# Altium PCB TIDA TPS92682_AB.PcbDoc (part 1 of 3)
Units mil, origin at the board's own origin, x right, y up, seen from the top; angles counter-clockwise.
Board outline 3149 x 2999 mil, 6 copper layers (Top Layer, Signal Layer 1, Signal Layer 2, Signal Layer 3, Signal Layer 4, Bottom Layer), stack 61.4 mil thick; 281 components, 181 nets, 796 pads, 814 vias.
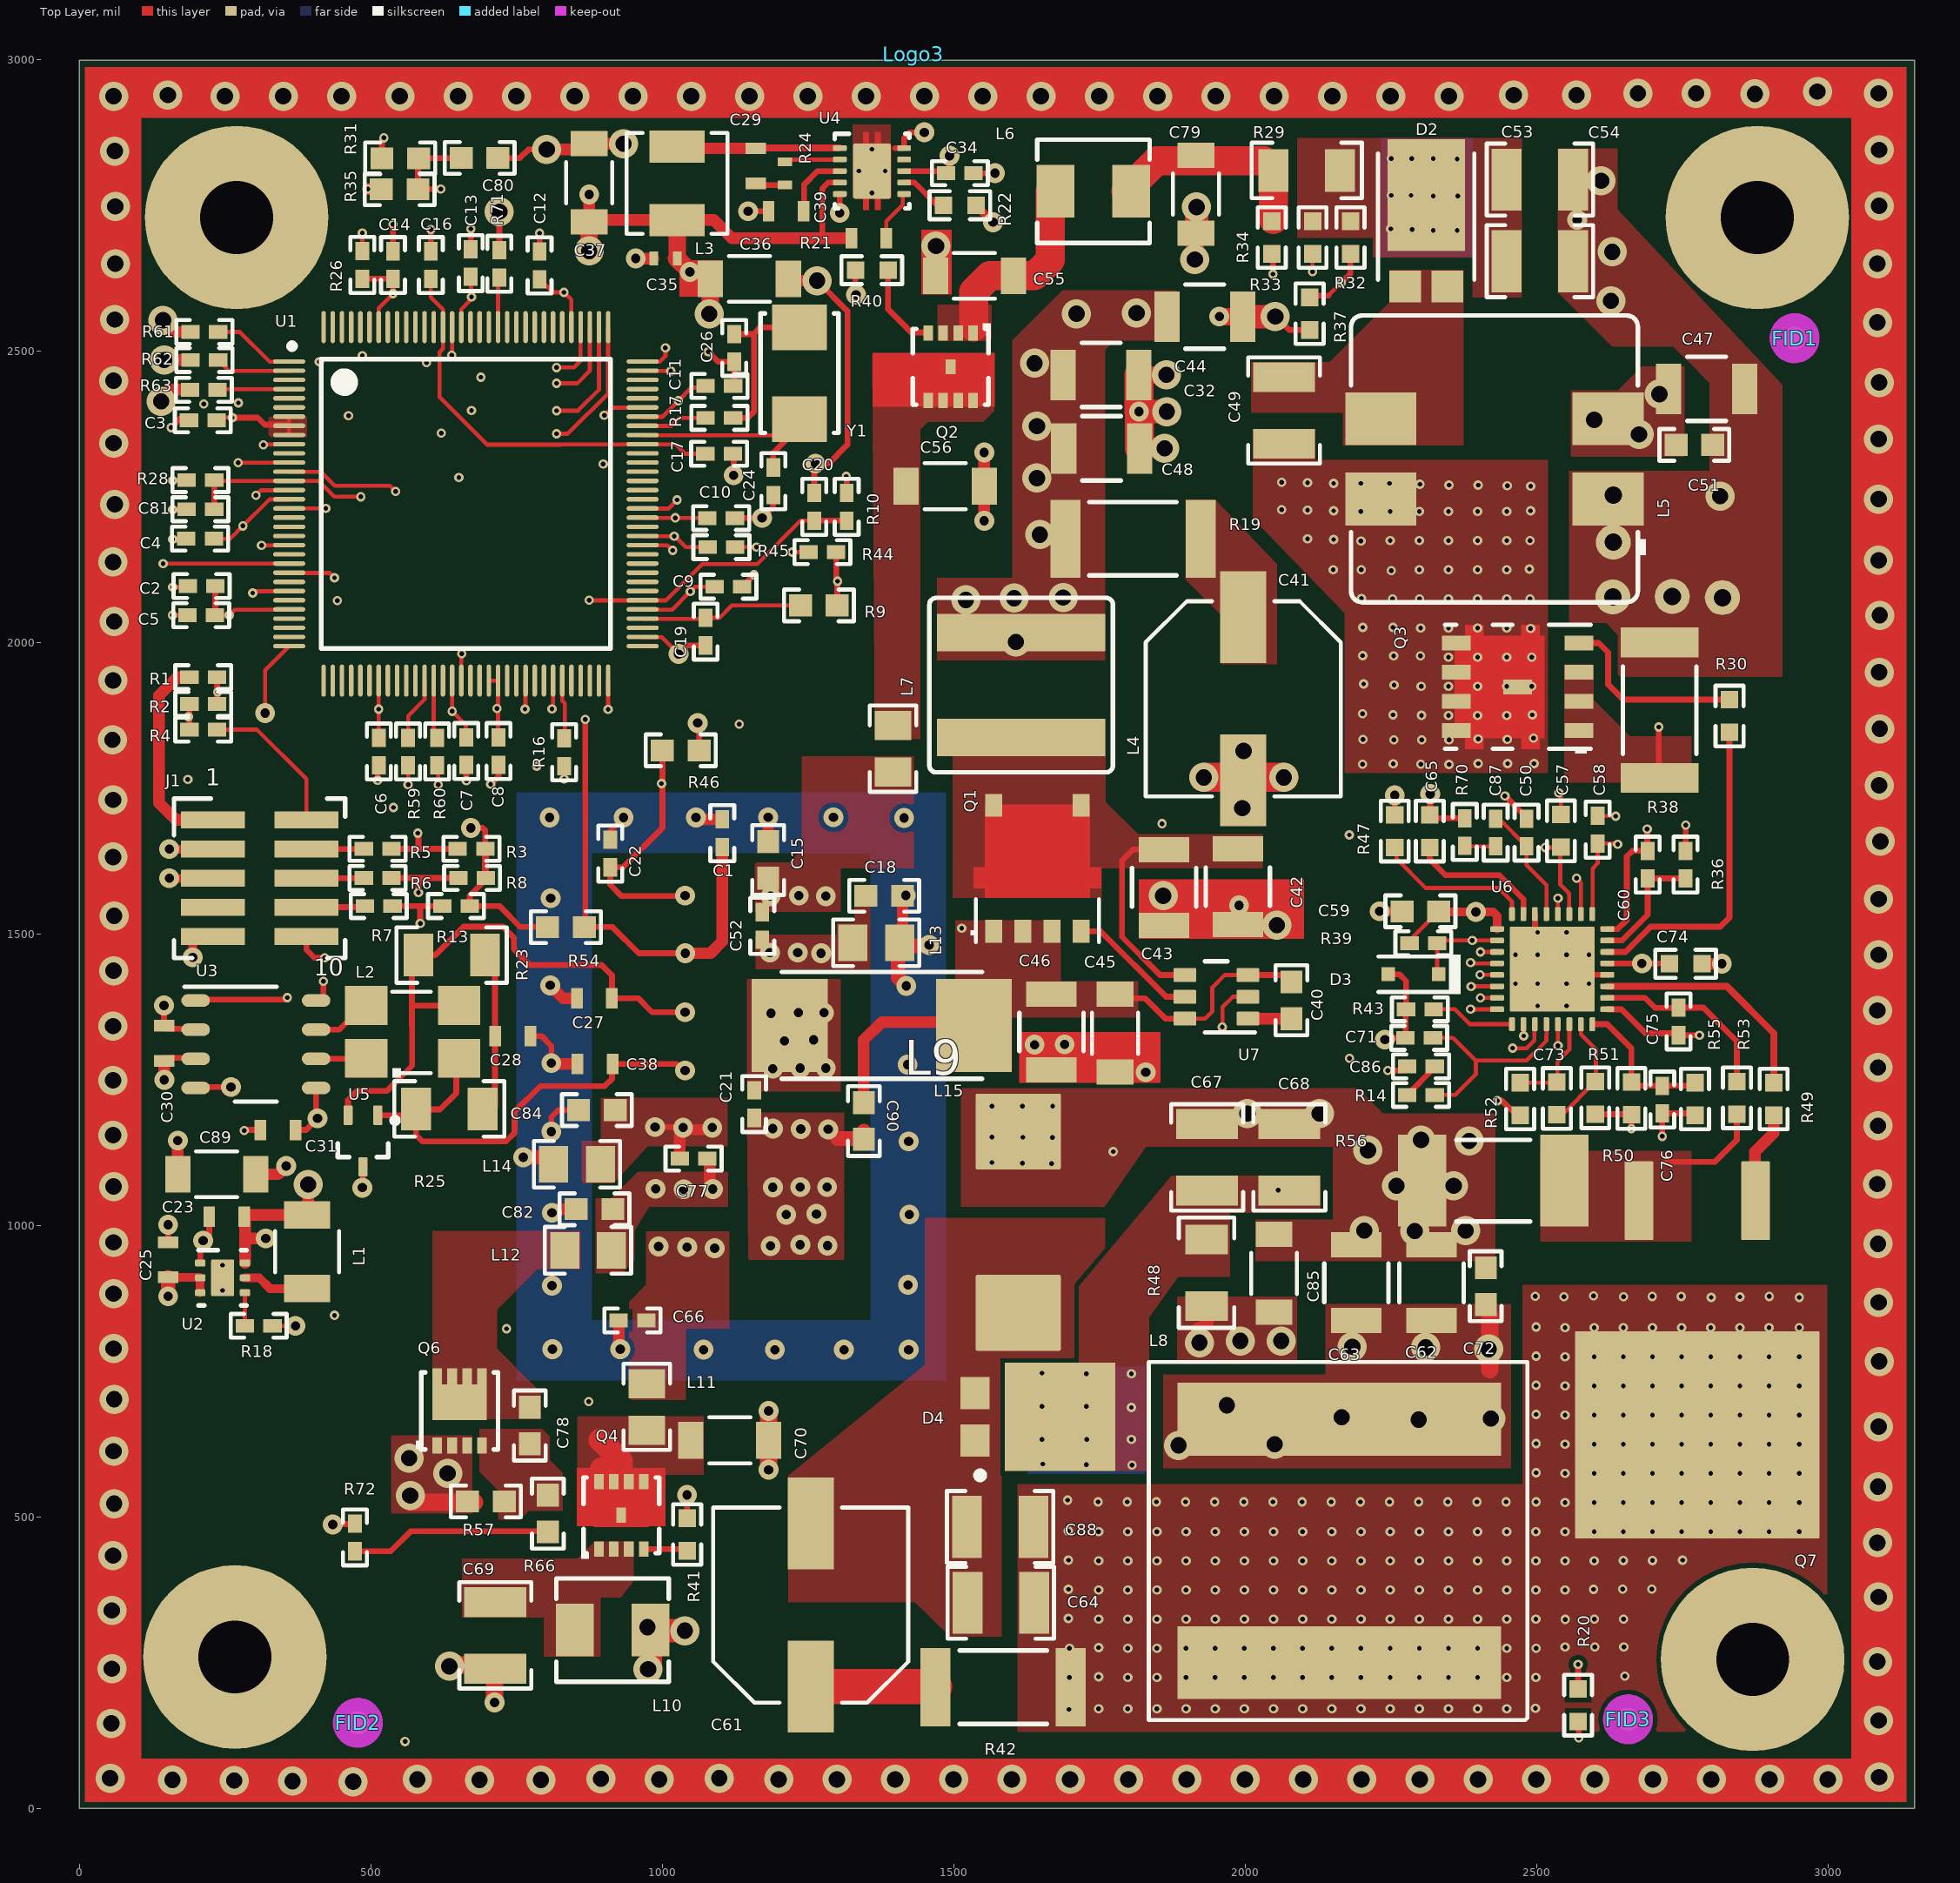
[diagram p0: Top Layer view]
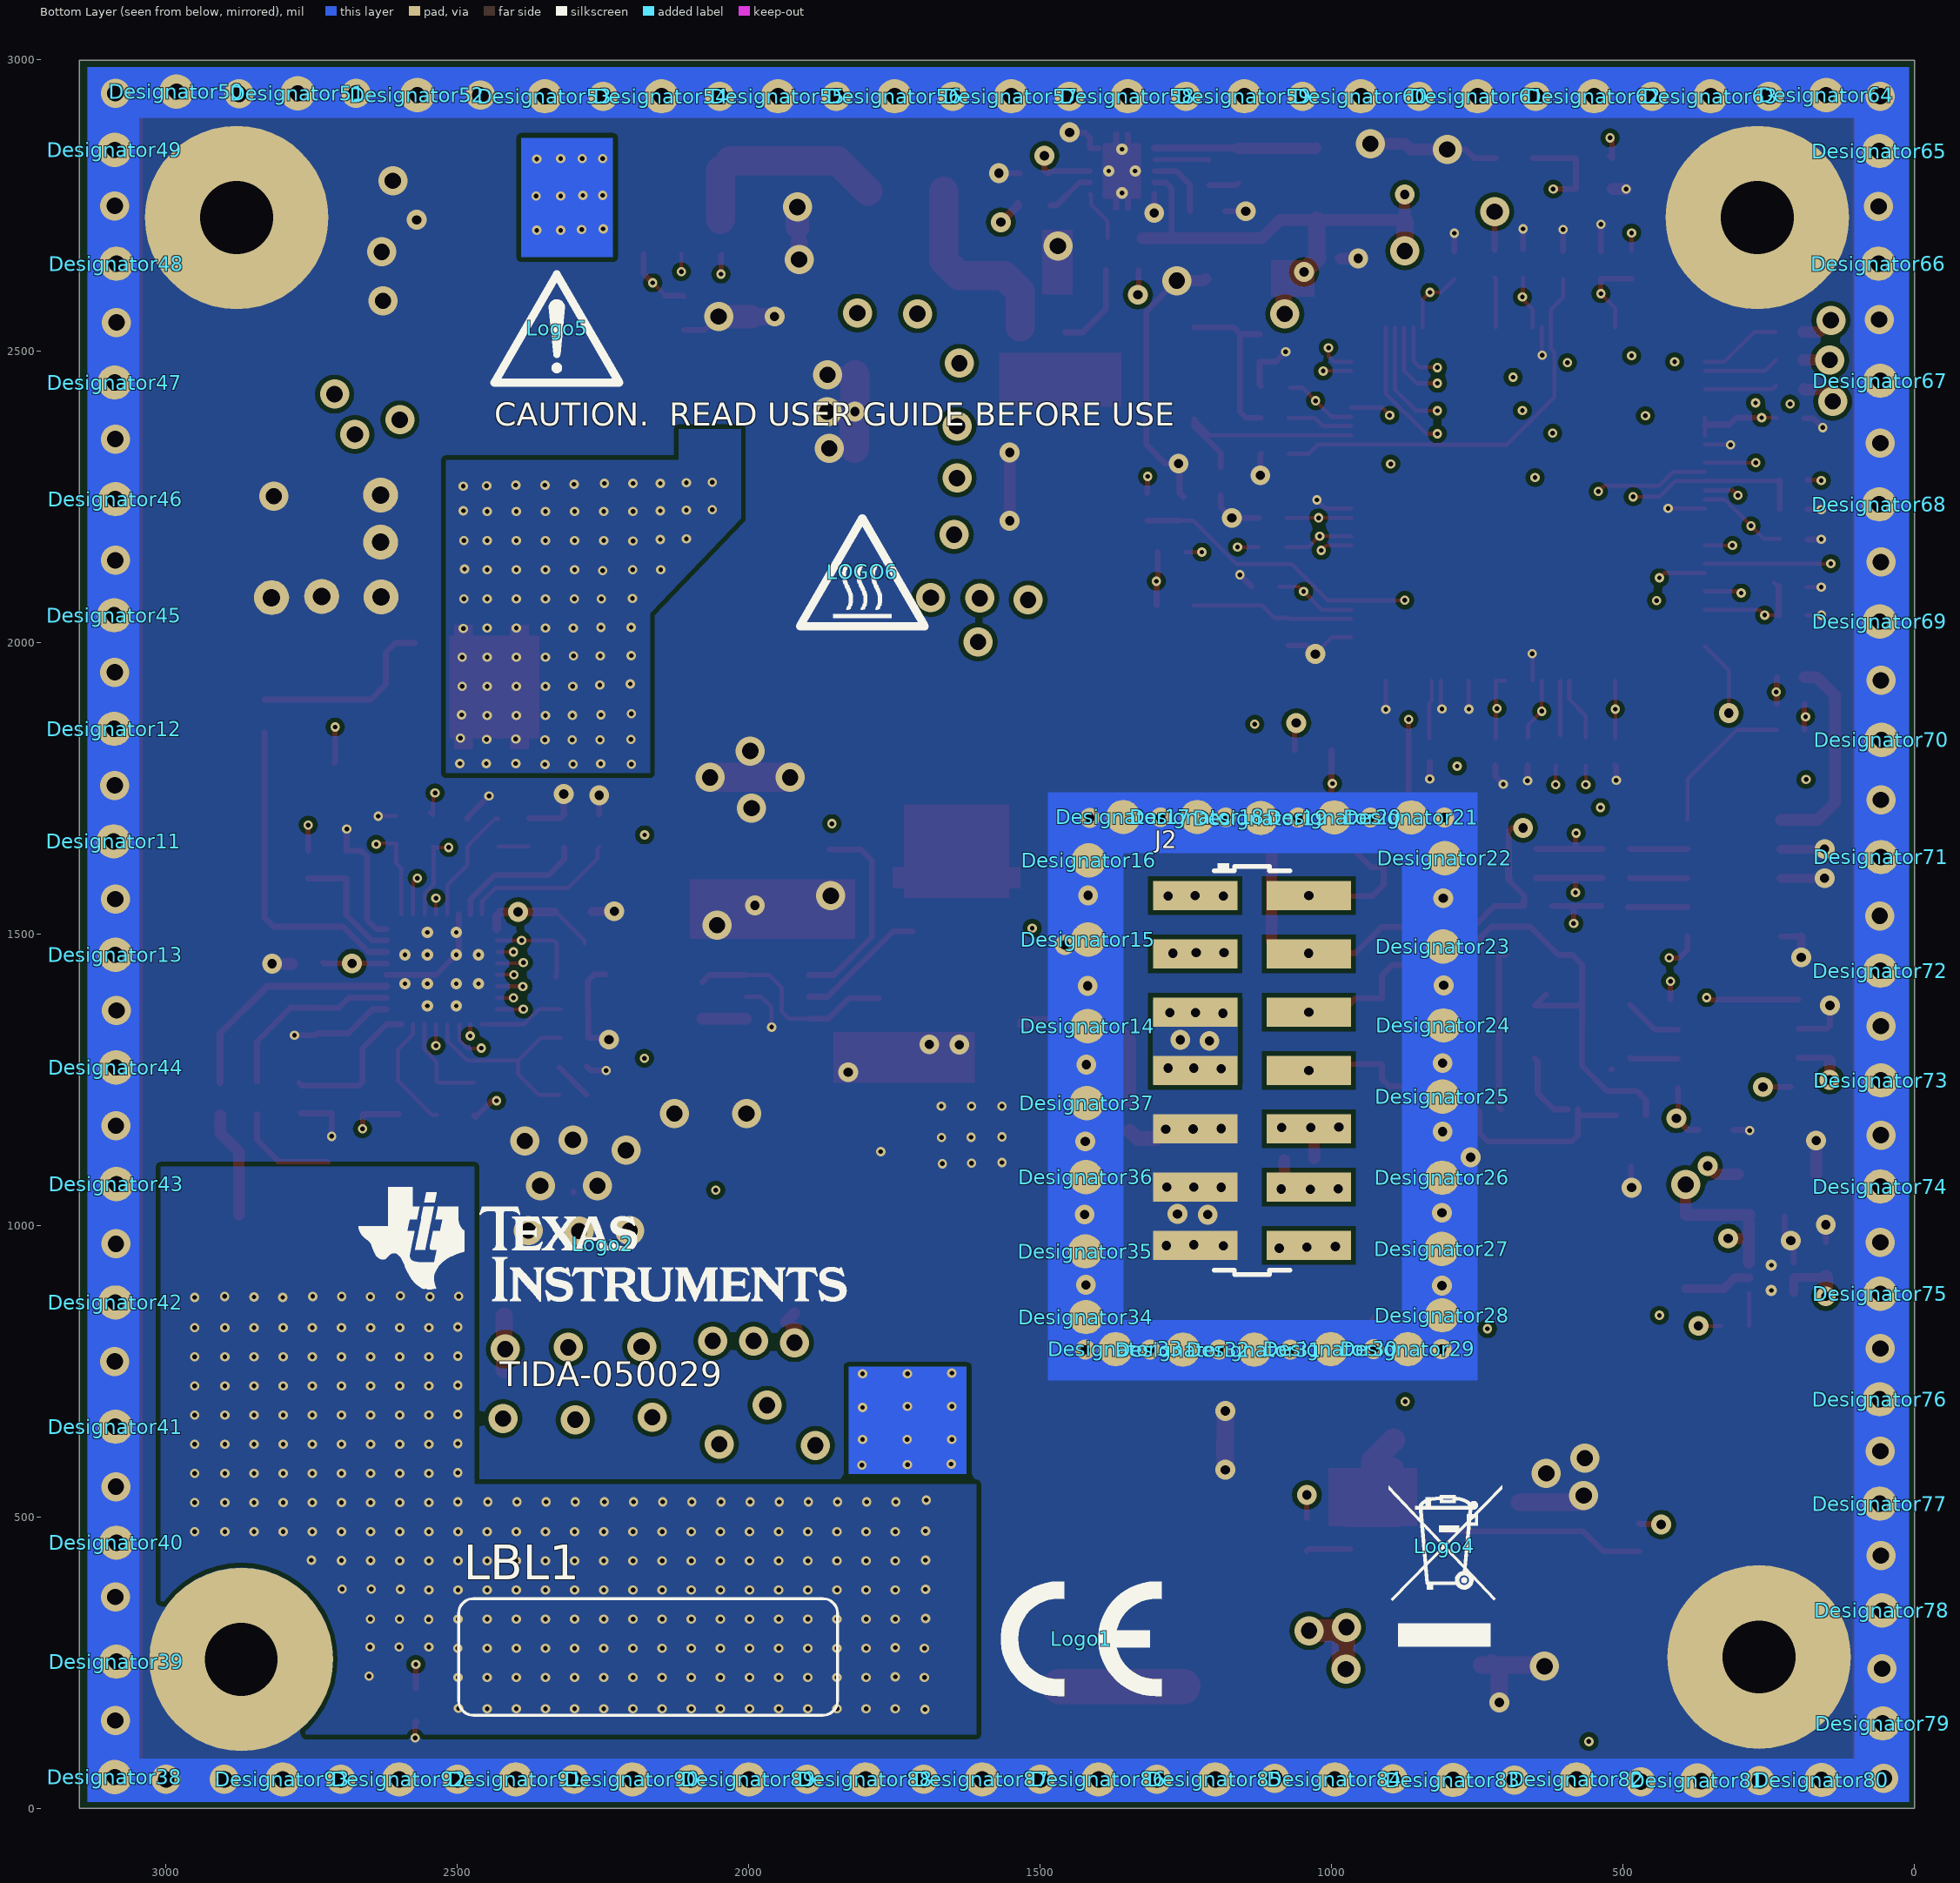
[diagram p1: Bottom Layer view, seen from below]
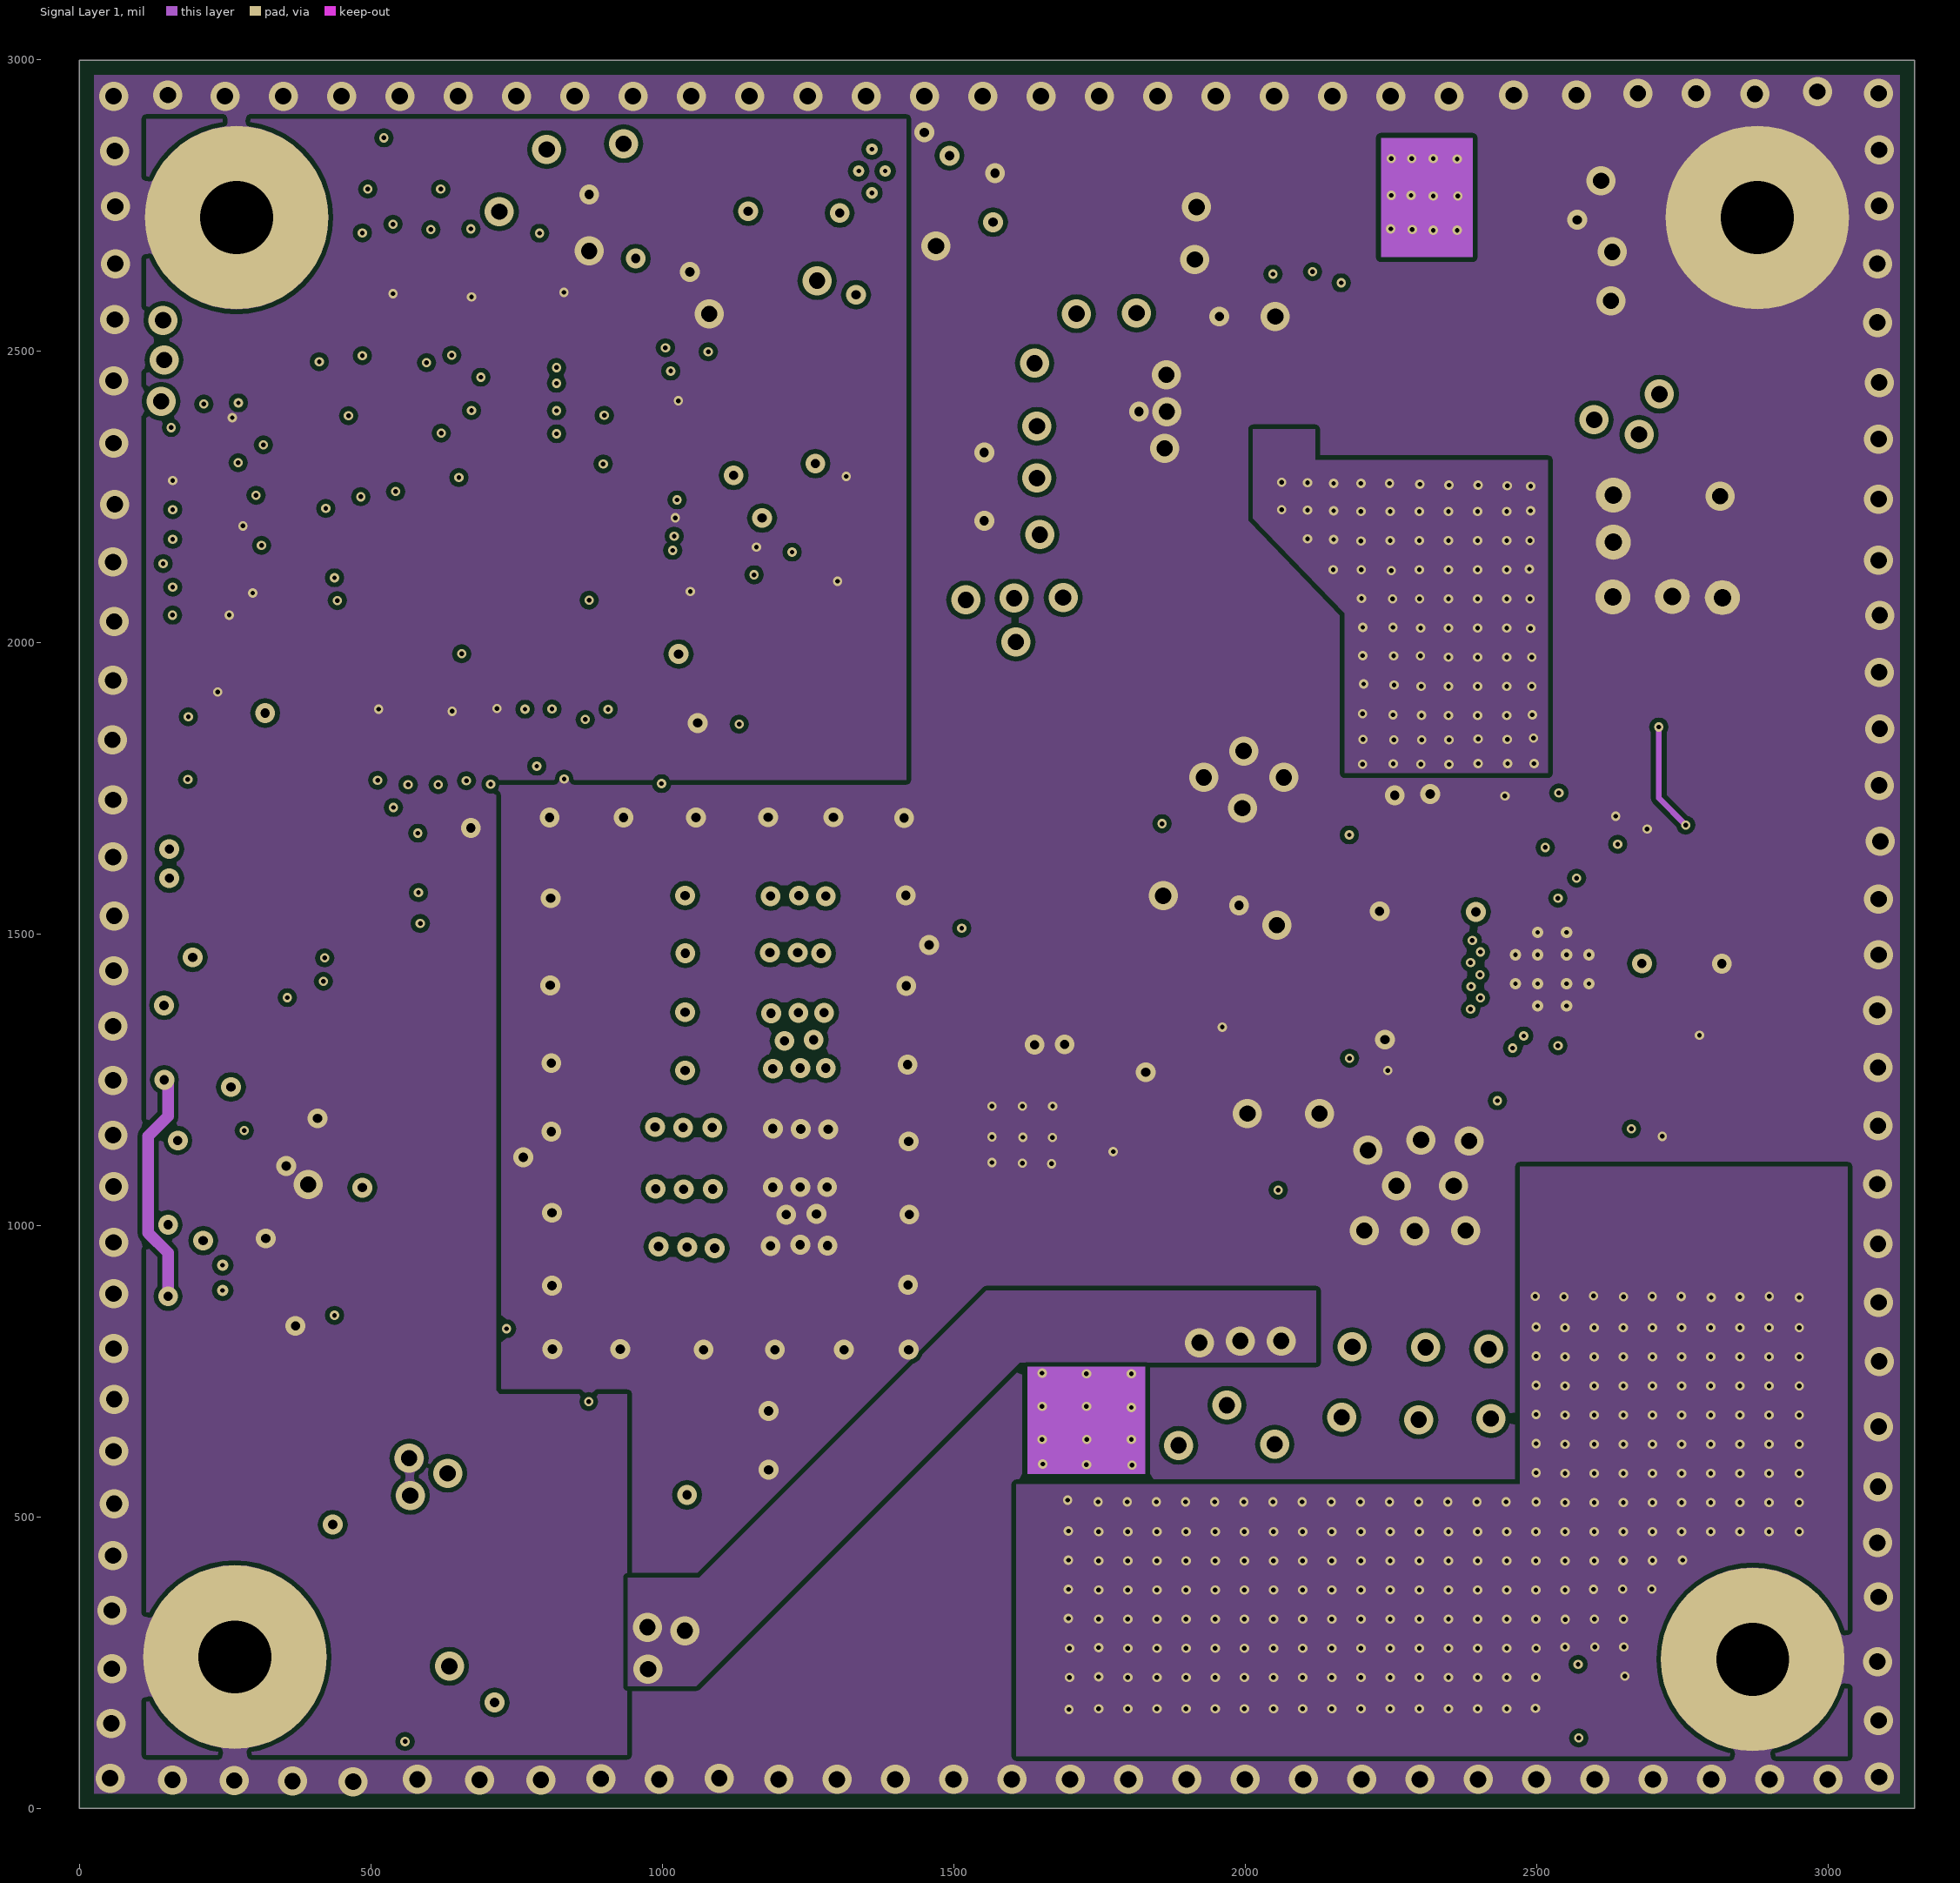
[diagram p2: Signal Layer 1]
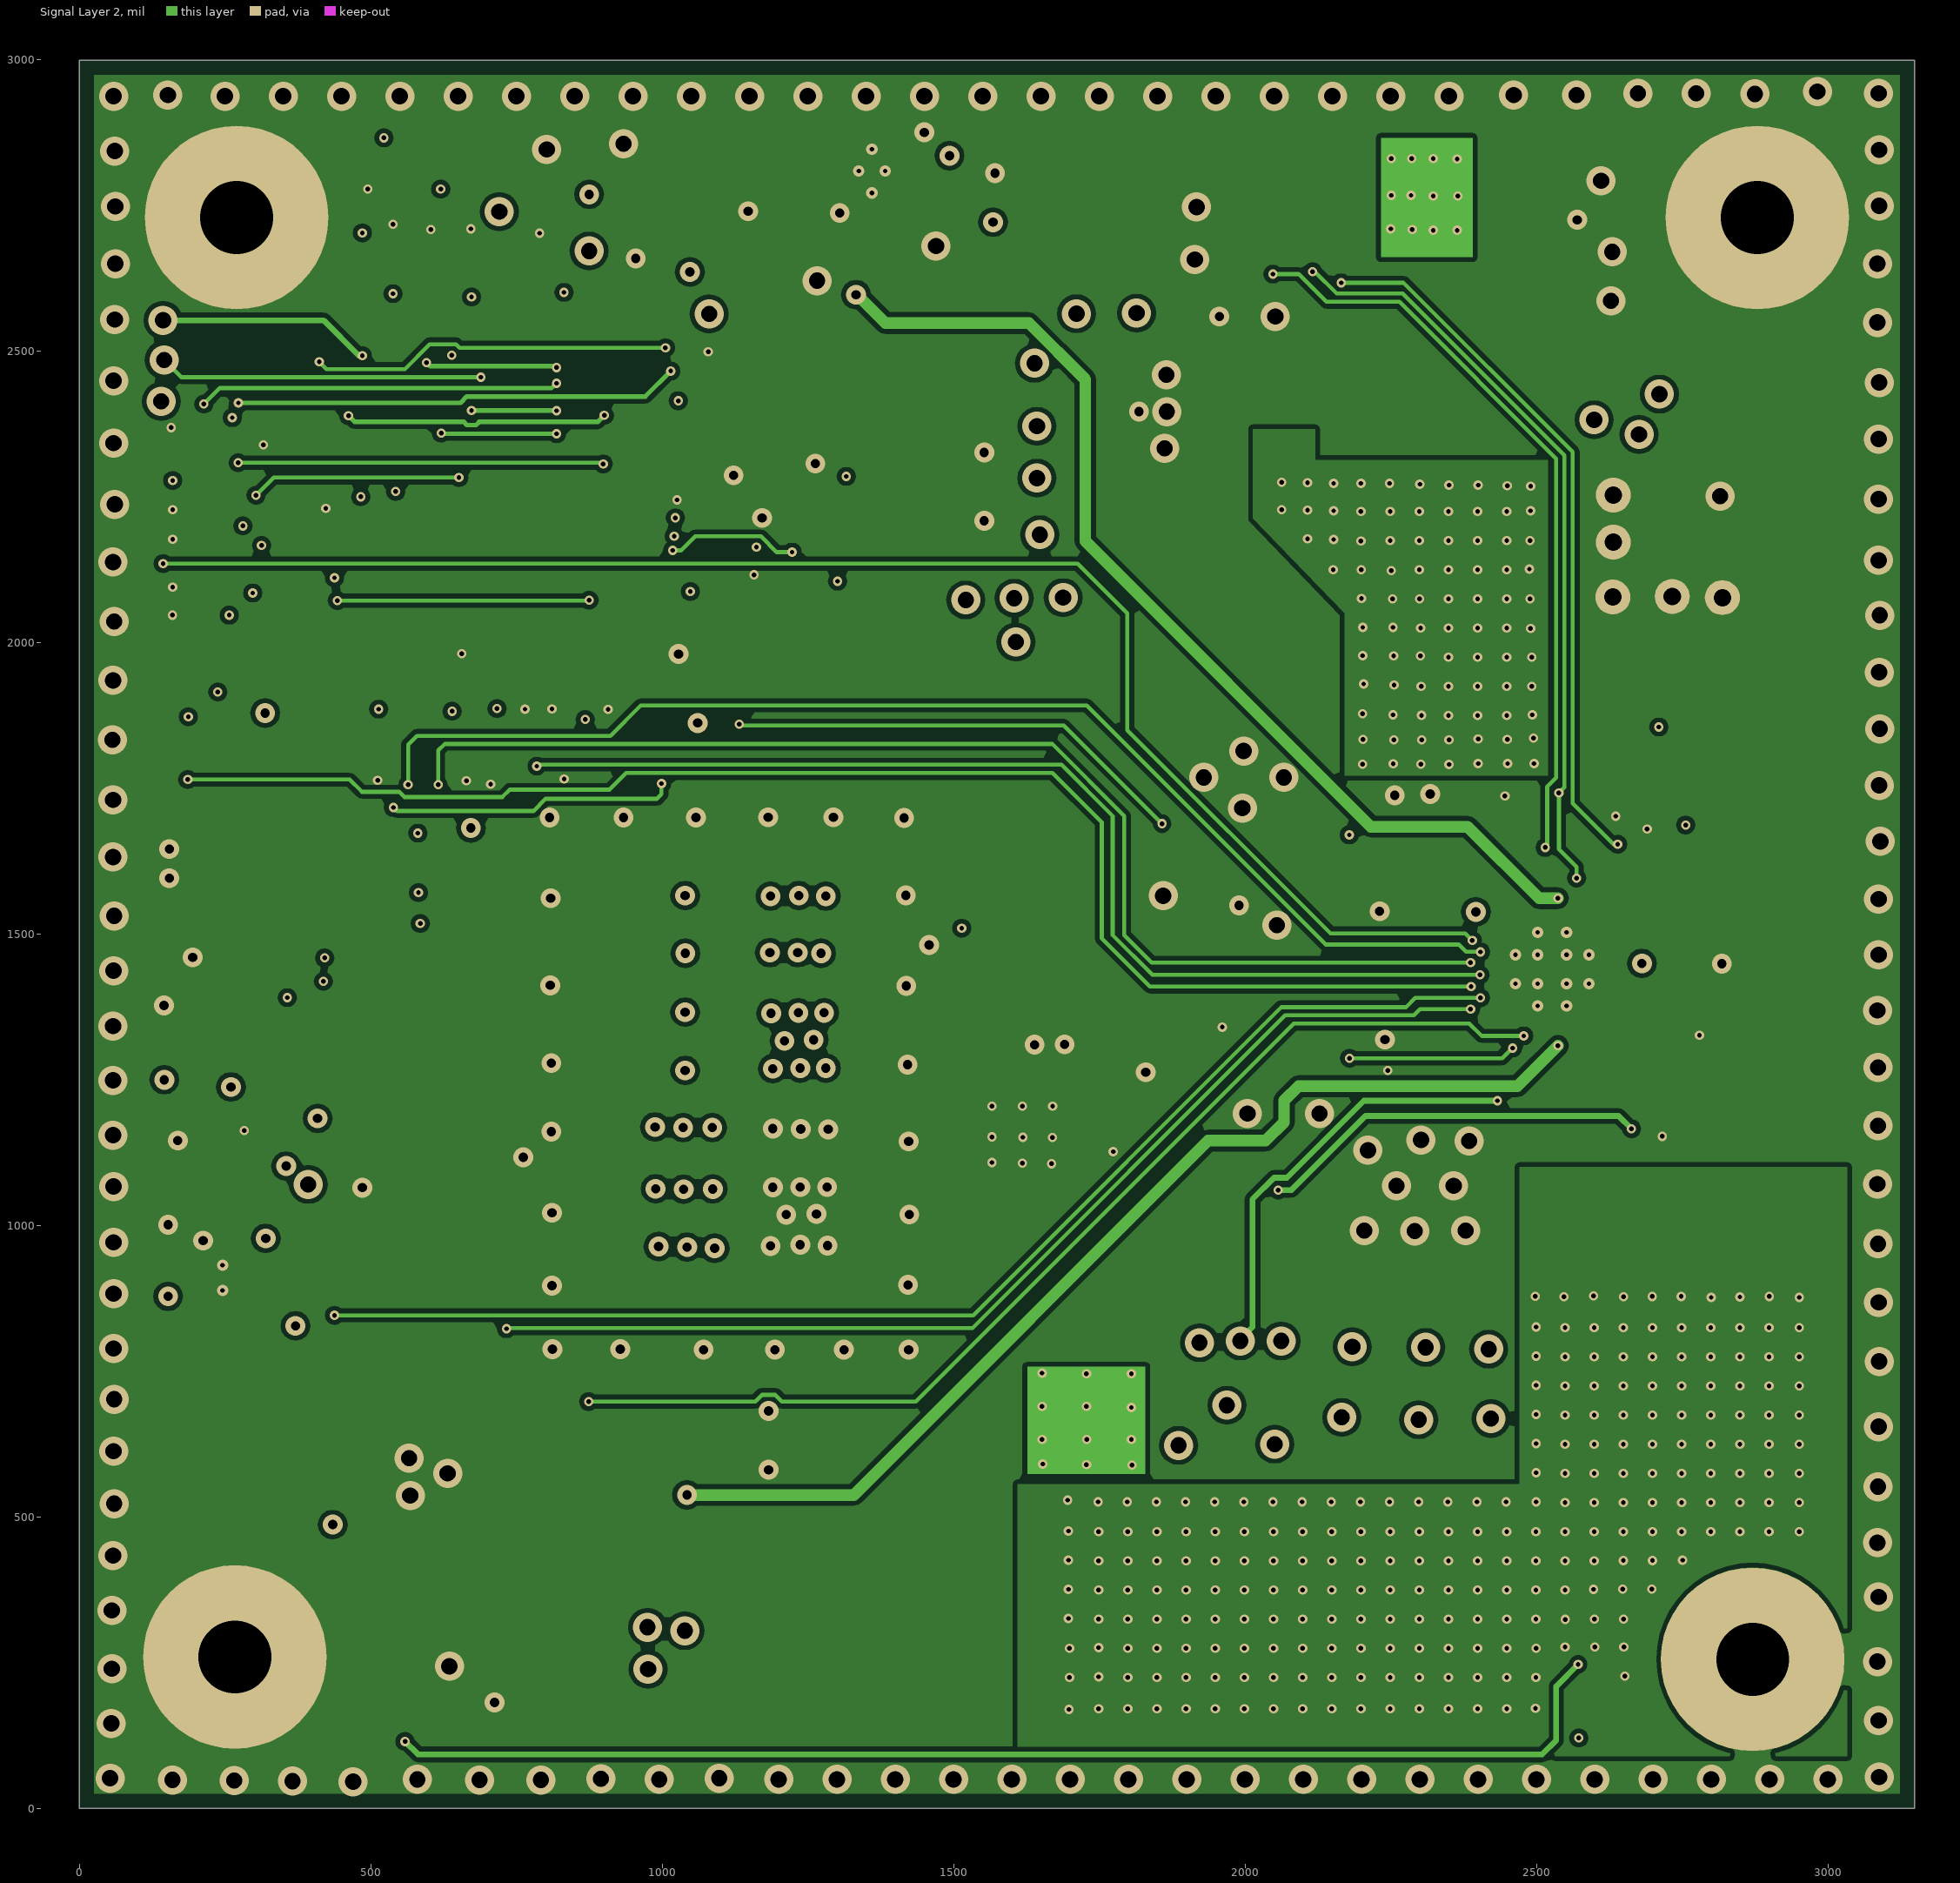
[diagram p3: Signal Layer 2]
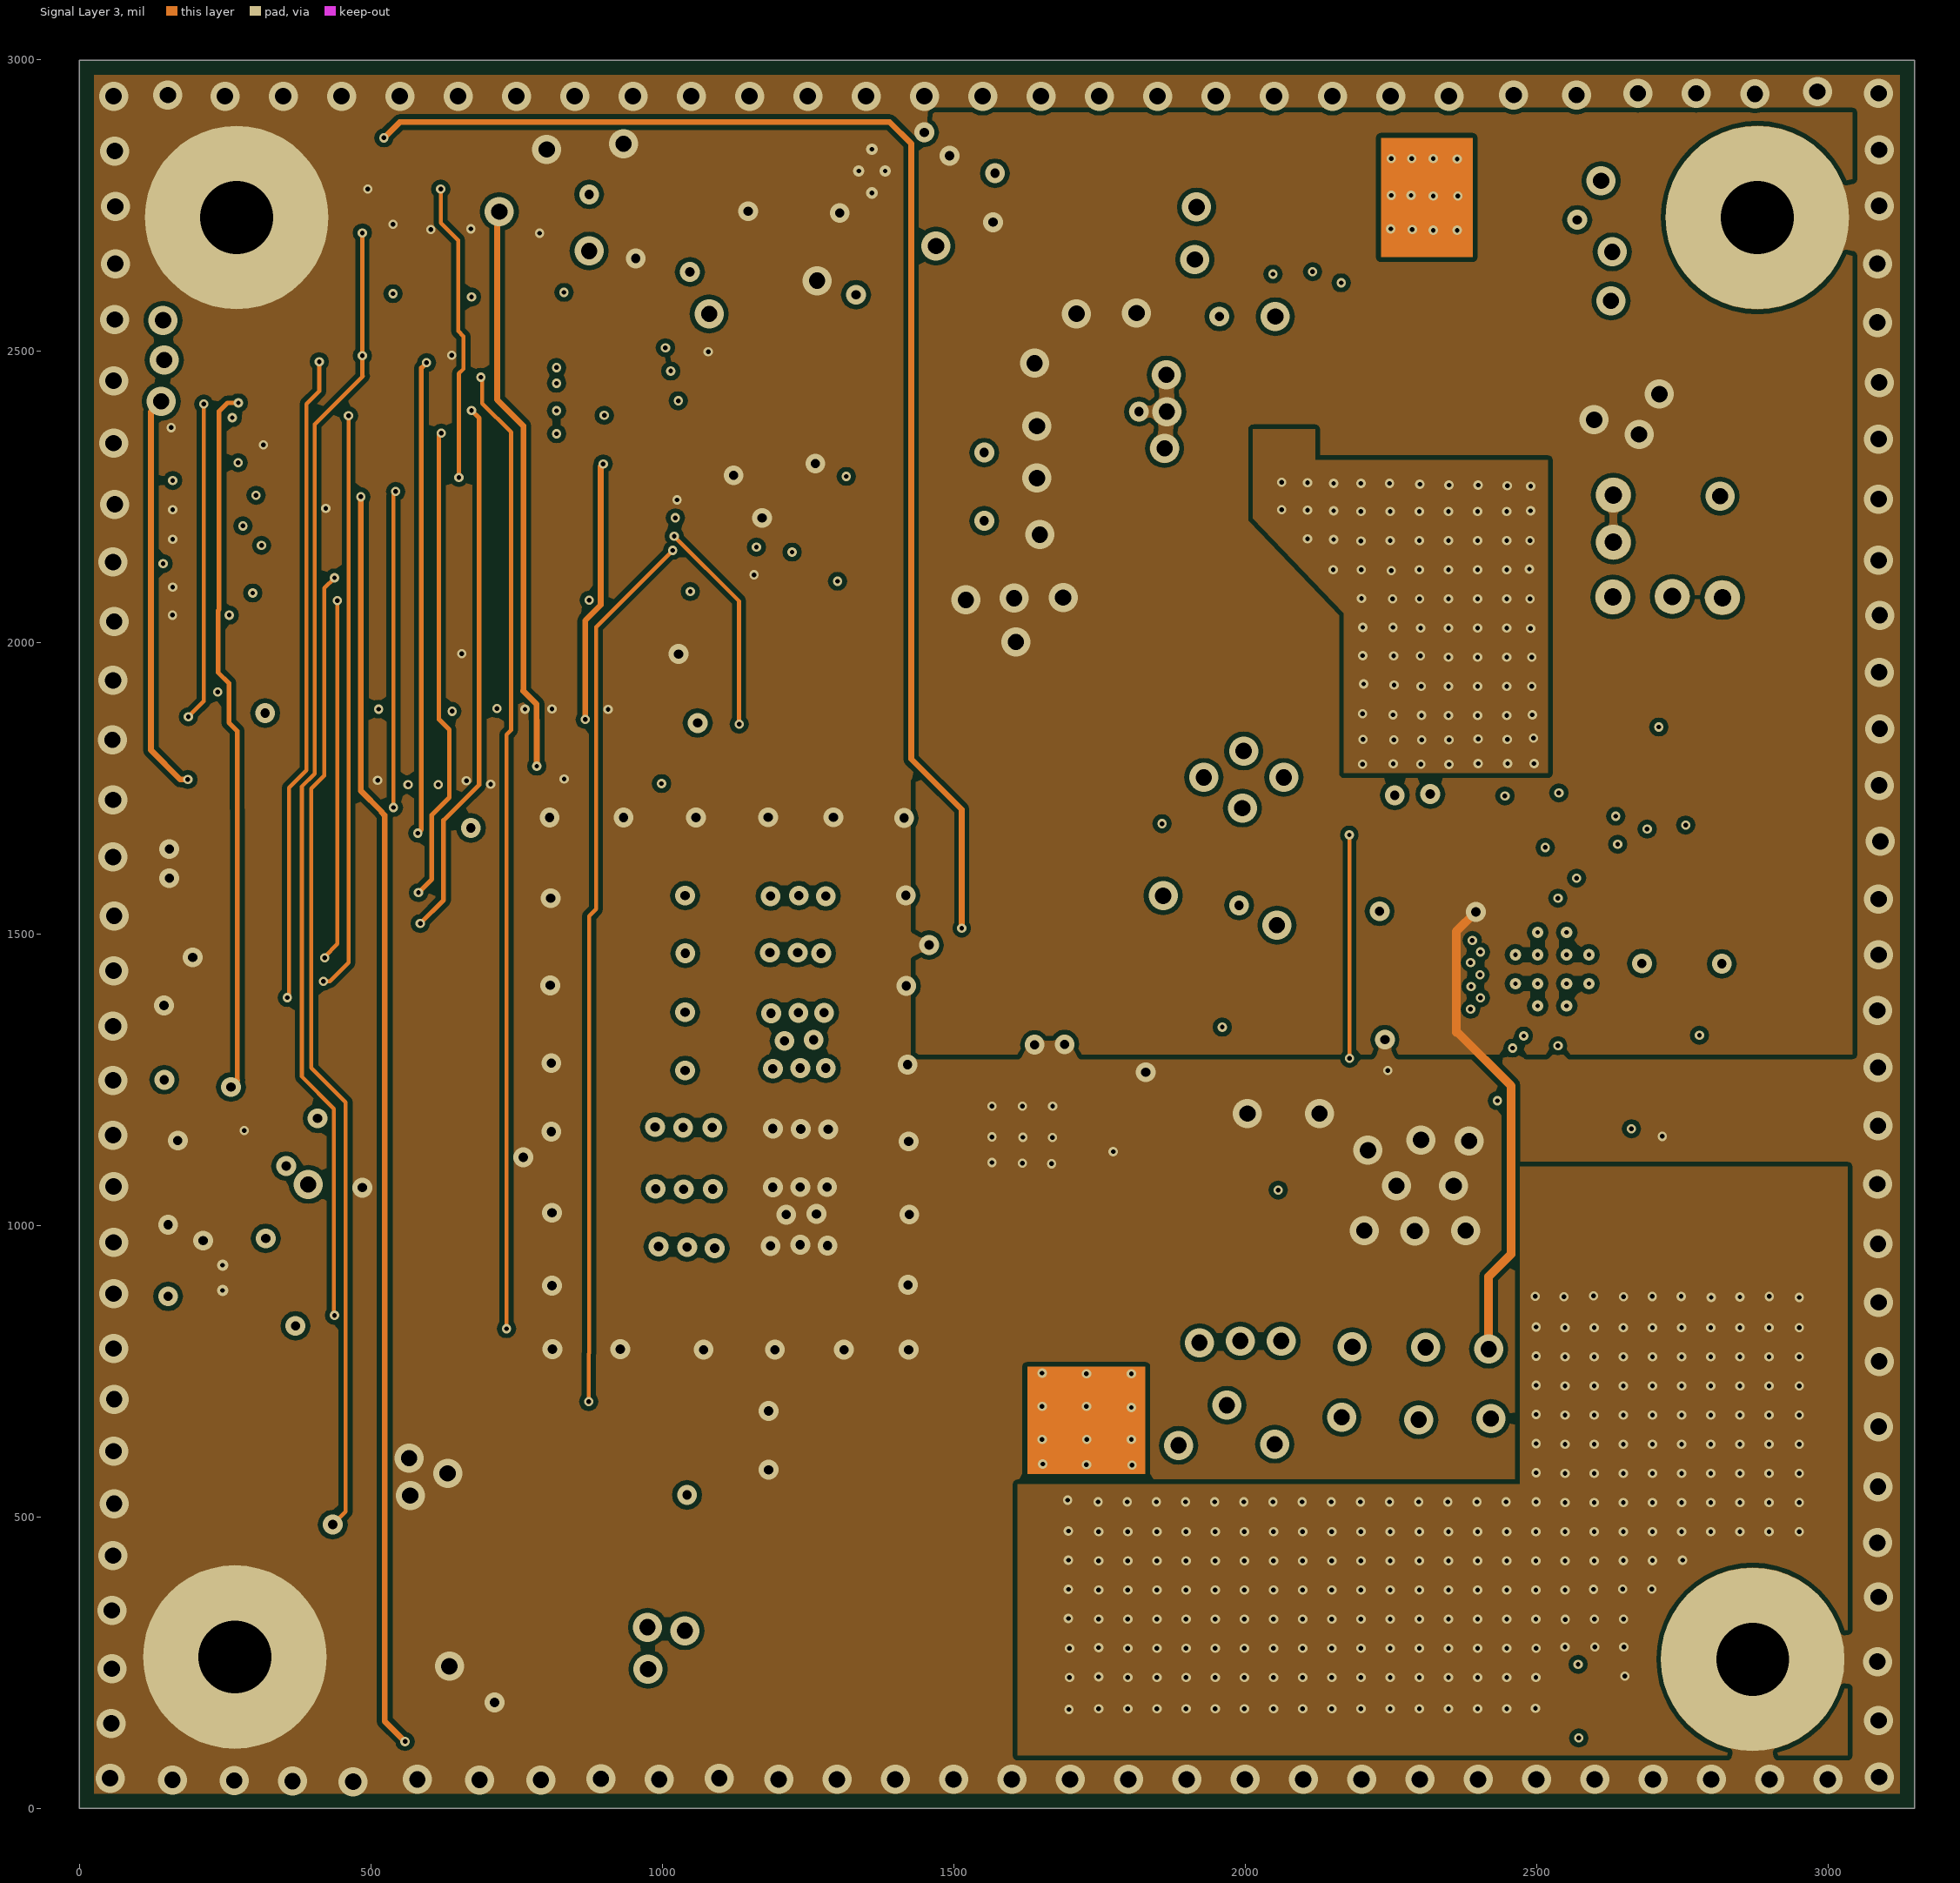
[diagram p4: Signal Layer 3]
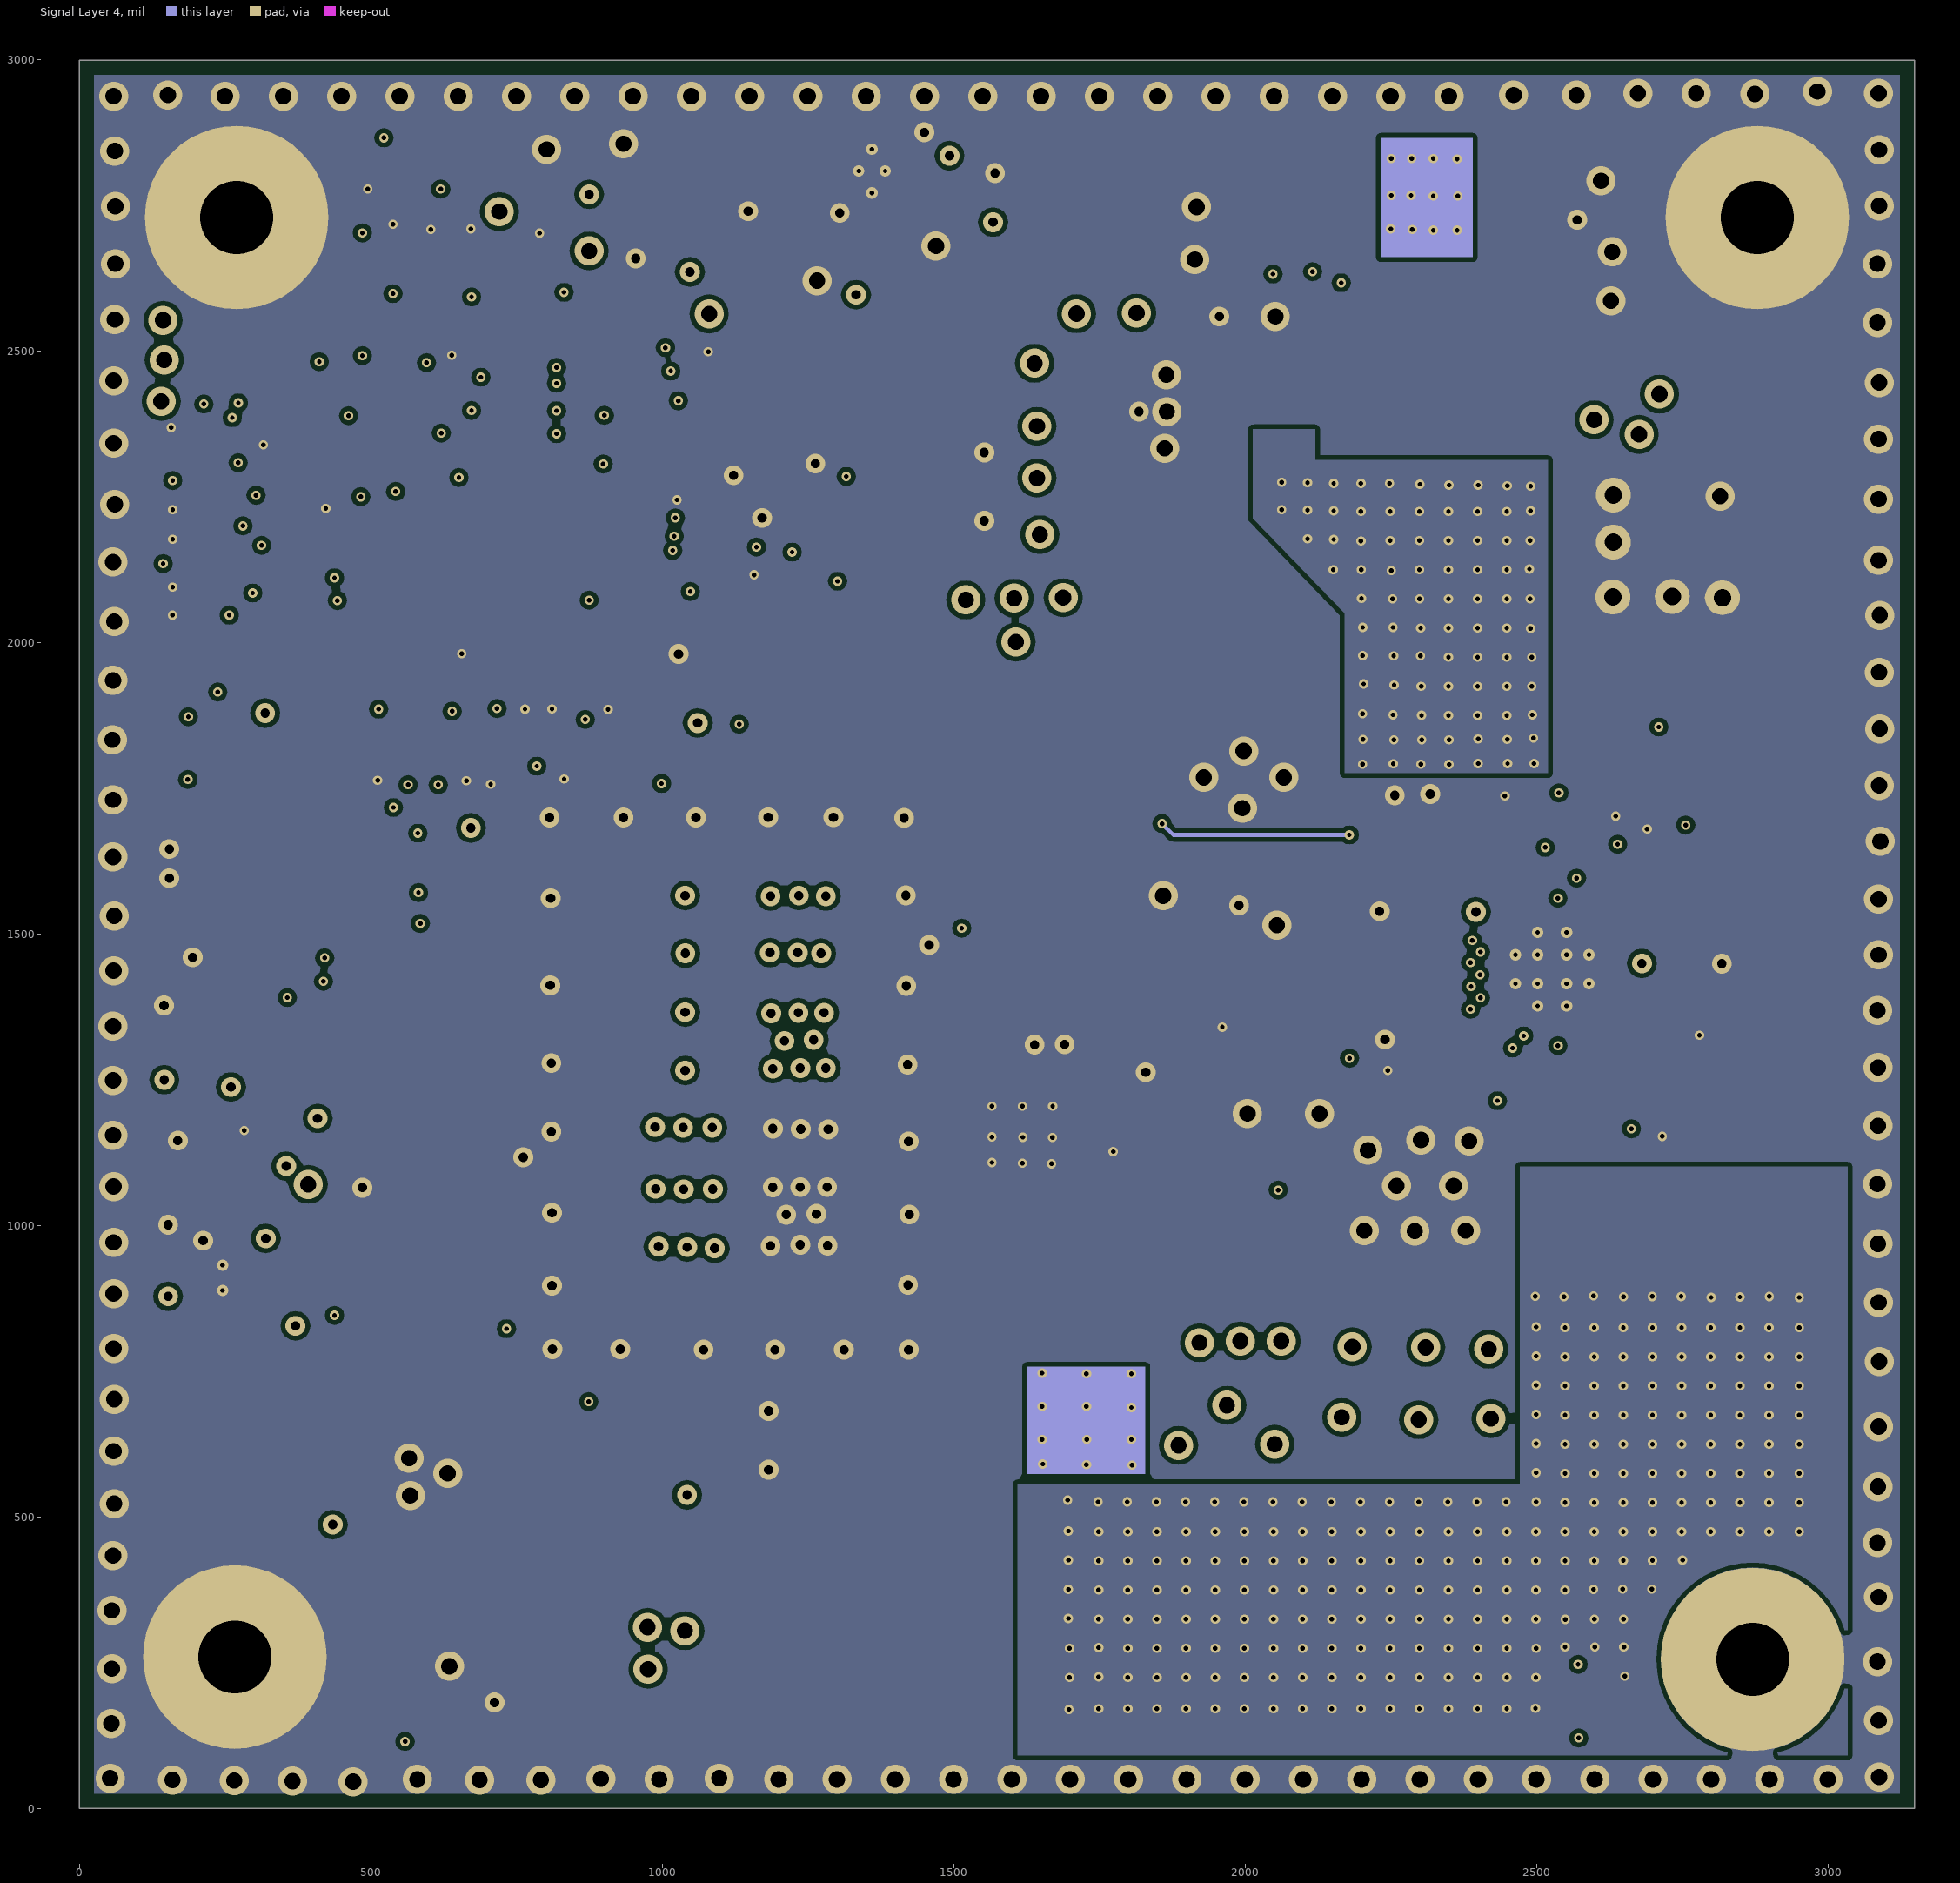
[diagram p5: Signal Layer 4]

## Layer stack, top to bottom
Top Solder: solder mask 0.5, Solder Resist, Dk 3.5
Top Layer: signal copper 1.4
Dielectric 1: prepreg 7, FR-4, Dk 4.2
Signal Layer 1: signal copper 1.4
Dielectric 2: core 14, FR-4, Dk 4.2
Signal Layer 2: signal copper 1.4
Dielectric 4: prepreg 11, FR-4, Dk 4.2
Signal Layer 3: signal copper 1.4
Dielectric 5: core 14, FR-4, Dk 4.2
Signal Layer 4: signal copper 1.4
Dielectric 3: prepreg 7, FR-4, Dk 4.2
Bottom Layer: signal copper 1.4
Bottom Solder: solder mask 0.5, Solder Resist, Dk 3.5

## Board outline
0,0 0,2999 3149,2999 3149,0

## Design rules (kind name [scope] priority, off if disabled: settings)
AcuteAngle [All] p1: minimum=4.50000000000000E+0001 checktracksonly=FALSE
AssemblyTestPointUsage [All] p1: valid=2
BoardOutlineClearance BoardOutlineClearance_MountingHoles [OnCopper and InComponentClass('Mounting Holes')] p1: gap=40 ignorepadtopadclearanceinfootprint=FALSE
BoardOutlineClearance BoardOutlineClearance_Poly [OnCopper and IsPoly] p2: gap=25 ignorepadtopadclearanceinfootprint=FALSE
BoardOutlineClearance [OnCopper and Not InComponentClass('Logo') and not InComponentClass('FiducialMark') and not InRegion(1000,500,4000,800) and not InPoly] p3: gap=40 ignorepadtopadclearanceinfootprint=FALSE
Clearance Clearance_Keepouts [((IsTrack Or IsArc) And Not InPoly) And IsFree and IsKeepOut vs ((IsTrack Or IsArc) And Not InPoly) And IsFree and IsKeepOut] p1: gap=0 ignorepadtopadclearanceinfootprint=FALSE
Clearance Clearance_Poly [InPolygon] p2: gap=8 ignorepadtopadclearanceinfootprint=FALSE except(0: Arc-Hole Track-Hole SMDPad-Hole THPad-Hole Via-Hole Fill-Hole Poly-Hole Region-Hole Text-Hole)
Clearance Clearance_FiducialMark [IsKeepOut and InComponentClass('FiducialMark') vs IsPad and InComponentClass('FiducialMark')] p3: gap=0 ignorepadtopadclearanceinfootprint=FALSE
Clearance [All] p4: gap=7 ignorepadtopadclearanceinfootprint=FALSE except(0: Arc-Hole Track-Hole SMDPad-Hole THPad-Hole Via-Hole Fill-Hole Poly-Hole Region-Hole Text-Hole)
ComponentClearance ComponentClearance_MountingHoles_FiducialMarks [InComponentClass('Mounting Holes') vs InComponentClass('FiducialMark')] p1: gap=50 collisioncheckmode=3 verticalgap=10 showdistances=FALSE
ComponentClearance ComponentClearance_Shunt [InComponentClass('Header') vs InComponentClass('Shunt')] p2: gap=0 collisioncheckmode=3 verticalgap=0 showdistances=FALSE
ComponentClearance ComponentClearance_Logo [InComponentClass('Logo')] p3: gap=50 collisioncheckmode=3 verticalgap=10 showdistances=FALSE
ComponentClearance ComponentClearance_ScrewToNut [(HasFootprint('NY PMS 440 0025 PH')) vs (HasFootprint('Keystone_1902C'))] p4: gap=5 collisioncheckmode=3 verticalgap=10 showdistances=FALSE
ComponentClearance ComponentClearance_MountingHoles [InComponentClass('Mounting Holes')] p5: gap=250 collisioncheckmode=3 verticalgap=100000 showdistances=FALSE
ComponentClearance ComponentClearance_SmallPassives [HasFootprint('0201*') or HasFootprint('0402*') or HasFootprint('0508') or HasFootprint('0603*') or HasFootprint('0612') or HasFootprint('0805*') or HasFootprint('0815*') or HasFootprint('0830*') or HasFootprint('1206*') or HasFootprint('1210*') or HasFootprint('1808*') or HasFootprint('1812*') or HasFootprint('1825*') or HasFootprint('2010*') or HasFootprint('2220*') or HasFootprint('2225*') or HasFootprint('2512*') or HasFootprint('2728*') or HasFootprint('3518*') vs HasFootprint('0201*') or HasFootprint('0402*') or HasFootprint('0508') or HasFootprint('0603*') or HasFootprint('0612') or HasFootprint('0805*') or HasFootprint('0815*') or HasFootprint('0830*') or HasFootprint('1206*') or HasFootprint('1210*') or HasFootprint('1808*') or HasFootprint('1812*') or HasFootprint('1825*') or HasFootprint('2010*') or HasFootprint('2220*') or HasFootprint('2225*') or HasFootprint('2512*') or HasFootprint('2728*') or HasFootprint('3518*')] p6: gap=14.96 collisioncheckmode=3 verticalgap=10 showdistances=FALSE
ComponentClearance ComponentClearance_THtoSMT [IsThruComponent vs IsSMTComponent] p7: gap=40 collisioncheckmode=3 verticalgap=30 showdistances=FALSE
ComponentClearance ComponentClearance_THtoTH [IsThruComponent vs IsThruComponent] p8: gap=30 collisioncheckmode=3 verticalgap=30 showdistances=FALSE
ComponentClearance [All] p9: gap=15 collisioncheckmode=3 verticalgap=10 showdistances=FALSE
DiffPairsRouting [All] p1: maxlimit=100 minlimit=10 mostfreqgap=10 toplayer_minwidth=15 toplayer_maxwidth=15 toplayer_prefwidth=15 midlayer1_minwidth=15 midlayer1_maxwidth=15 midlayer1_prefwidth=15 midlayer2_minwidth=15 midlayer2_maxwidth=15 midlayer2_prefwidth=15 midlayer3_minwidth=15 midlayer3_maxwidth=15 midlayer3_prefwidth=15 midlayer4_minwidth=15 midlayer4_maxwidth=15 midlayer4_prefwidth=15 bottomlayer_minwidth=15 bottomlayer_maxwidth=15 bottomlayer_prefwidth=15 maxuncoupledlength=1000
FabricationTestPointUsage TestPointUsage [All] p1: valid=2 allowmultiple=FALSE
FabricationTestpoint Testpoint [All] p1: side=3 testpointundercomponent=TRUE minsize=40 maxsize=100 preferedsize=60 minholesize=0 maxholesize=40 preferedholesize=32 testpointgrid=1 allowsidetop=TRUE allowsidebottom=TRUE usegrid=TRUE gridtolerance=0.01
FanoutControl Fanout_LCC [IsLCC] p1: bgadir=Out bgaviamode=Centered fanoutstyle=Auto fanoutdirection=Alternating viagrid=1 // Fanout_LCC (Default Rule)
FanoutControl Fanout_BGA [IsBGA] p2: bgadir=Out bgaviamode=Centered fanoutstyle=Auto fanoutdirection=Alternating viagrid=1 // Fanout_BGA (Default Rule)
FanoutControl Fanout_Default [All] p4: bgadir=Out bgaviamode=Centered fanoutstyle=Auto fanoutdirection=Alternating viagrid=1 // Fanout_Default (Default Rule)
FanoutControl Fanout_Small [(CompPinCount < 5)] p5: bgadir=Out bgaviamode=Centered fanoutstyle=Auto fanoutdirection=OutThenIn viagrid=1 // Fanout_Small (Default Rule)
HoleSize [All] p1: absolutevalues=TRUE maxlimit=251 minlimit=7.87 maxpercent=80.000 minpercent=20.000
MinimumAnnularRing MinimumAnnularRing_ThermalPadVias [IsVia and InAnyComponent] p1: minimumring=5.91
MinimumAnnularRing [All] p2: minimumring=4
MinimumSolderMaskSliver MinimumSolderMaskSliver_Logo [InComponentClass('Logo') vs InComponentClass('Logo')] p1: minsoldermaskwidth=0.7
MinimumSolderMaskSliver [All] p2: minsoldermaskwidth=3.94
PlaneConnect [All] p1: planeconnectstyle=Relief reliefexpansion=10 reliefentries=4 reliefconductorwidth=10 reliefairgap=10
PolygonConnect [All] p1: connectstyle=Direct reliefconductorwidth=10 reliefentries=4 polygonreliefangle="90 Angle" airgapwidth=10
RoutingVias ThermalPadVias [IsVia and InAnyComponent] p1: holewidth=7.87 width=19.68 viastyle="Through Hole" minholewidth=7.87 minwidth=19.68 maxholewidth=12.99 maxwidth=23.62
RoutingVias [All] p2: holewidth=16 width=34 viastyle="Through Hole" minholewidth=7.87 minwidth=16 maxholewidth=40 maxwidth=65
SilkToBoardRegionClearance [Not ((IsComment or IsDesignator) And (Hide <> 'False')) and not InRegion(1000,500,4000,800)] p1:
SilkToSilkClearance SilkToSilkClearance_Pb-FreeLogo [(HasFootprint('Pb-Free_Overlay_Medium') OR HasFootprint('Pb-Free_Overlay_Small')) vs (HasFootprint('Pb-Free_Overlay_Medium') OR HasFootprint('Pb-Free_Overlay_Small'))] p1: silktosilkclearance=0
SilkToSilkClearance [All] p2: silktosilkclearance=4
SilkToSolderMaskClearance SilkToComponentPadClearance [(IsPad or IsFill or IsRegion) and InAnycomponent] p1: minsilkscreentomaskgap=5 clearancetoexposedcopper=TRUE
SilkToSolderMaskClearance "Silk to Solder Mask Opening" [All] p2: minsilkscreentomaskgap=4 clearancetoexposedcopper=FALSE
SolderMaskExpansion [All] p1: expansion=1.97
Width [All] p1: maxlimit=100 minlimit=6 preferedwidth=10 checkconnectedcopper=TRUE
15 further rules are at their usual default settings.

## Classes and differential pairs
component class Label: LBL1
component class AssemblyNote: ZZ1 ZZ2 ZZ3 ZZ4
component class FiducialMark: FID1 FID2 FID3
component class EVM_Hardware: FID1 FID2 FID3 LBL1 Logo1 Logo2 Logo3 Logo4 Logo5 LOGO6 ZZ1 ZZ2 ZZ3 ZZ4
component class Logo: Logo2
component class Header: J1 J2
component class TIDA_Sheet1: C1 C2 C3 C4 C5 C6 C7 C8 C9 C10 C11 C12 C13 C14 C16 C17 C19 C20 C22 C23 C24 C25 C26 C27 C28 C29 C30 C31 C32 C34 C35 C36 C37 C38 C39 C81 C89 J1 L1 L2 L3 R1 R2 R3 R4 R5 R6 R7 R8 R9 R10 R13 R16 R17 R18 R20 R21 R22 R23 R24 R25 R26 R28 R44 R45 R59 R60 R61 R62 R63 R71 R72 U1 U2 U3 U4 U5 Y1
component class TIDA_Sheet2: C15 C18 C21 C40 C41 C42 C43 C44 C45 C46 C47 C48 C49 C50 C51 C52 C53 C54 C55 C56 C57 C58 C59 C60 C61 C62 C63 C64 C65 C66 C67 C68 C69 C70 C71 C72 C73 C74 C75 C76 C77 C78 C79 C80 C82 C84 C85 C86 C87 C88 C90 D2 D3 D4 J2 L4 L5 L6 L7 L8 L9 L10 L11 L12 L13 L14 L15 Q1 Q2 Q3 Q4 Q6 Q7 R14 R19 R29 R30 R31 R32 R33 R34 R35 R36 R37 R38 R39 R40 R41 R42 R43 R46 R47 R48 R49 R50 R51 R52 R53 R54 R55 R56 R57 R66 R70 U6 U7

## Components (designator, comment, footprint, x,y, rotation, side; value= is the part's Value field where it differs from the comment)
C1 "CGA2B3X7R1H104M050BB" 0402 1103.26,1673 r90 top value=0.1uF
C2 "Capacitor" 0402 210,2097 r180 top value=0.1uF
C3 "Capacitor" 0402 212,2381 r180 top value=0.1uF
C4 "Capacitor" 0402 207.38,2178 r180 top value=0.1uF
C5 "Capacitor" 0402 209.38,2047 r180 top value=0.1uF
C6 "Capacitor" 0402 514.23,1813.07 r270 top value=0.1uF
C7 "Capacitor" 0402 664.11,1813.69 r270 top value=0.1uF
C8 "Capacitor" 0402 719.11,1813.69 r270 top value=0.1uF
C9 "Capacitor" 0402 1113.76,2095.63 r0 top value=0.1uF
C10 "Capacitor" 0402 1101.34,2213.49 r0 top value=0.1uF
C11 "Capacitor" 0402 1098.34,2440.27 r0 top value=0.1uF
C12 "Capacitor" 0402 789.76,2646.82 r90 top value=0.1uF
C13 "Capacitor" 0402 671.76,2650.82 r90 top value=0.1uF
C14 "Capacitor" 0402 538.34,2647.49 r90 top value=0.01uF
C15 "GRM188R72A103KA01D" 0603 1182,1627 r90 top value=0.01uF
C16 "Capacitor" 0402 603.34,2647.49 r90 top value=2.2uF
C17 "Capacitor" 0402 1097.76,2323.63 r0 top value=1uF
C18 "GRM188R72A103KA01D" 0603 1381,1565.71 r0 top value=0.01uF
C19 "Capacitor" 0402 1074.76,2018.63 r270 top value=0.1uF
C20 "Capacitor" 0402 1261,2232.72 r90 top value=0.01uF
C21 "CGA2B2X7R1H102K050BA" 0402 1157.88,1208.2 r270 top value=1000pF
C22 "CGA2B3X7R1H104M050BB" 0402 910.99,1638 r90 top value=0.1uF
C23 "Capacitor" 0603S 253,1015 r180 top value=2.2uF
C24 "Capacitor" 0402 1190.76,2276.63 r270 top value=22pF
C25 "Capacitor" 0603S 152.42,941.36 r90 top value=4.7uF
C26 "Capacitor" 0402 1123.76,2505.21 r270 top value=22pF
C27 "Capacitor" 0603S 884,1390 r180 top value=56pF
C28 "Capacitor" 0603S 744,1325 r0 top value=4700pF
C29 "Capacitor" 0603S 1160.76,2817.63 r90 top value=0.1uF
C30 "Capacitor" 0603S 145.58,1312.64 r90 top value=0.1uF
C31 "Capacitor" 0603S 341,1164 r180 top value=0.1uF
C32 "CGA6P3X7S1H106K250AB" 1210_280 1753,2459 r0 top value=10uF
C34 "Capacitor" 0402 1510.76,2804.9 r0 top value=0.01uF
C35 "Capacitor" 0402S 1005.76,2658.63 r180 top value=0.01uF
C36 "GCM31CR71A226KE02" 1206_180 1149.76,2623.63 r0 top value=22uF
C37 "GCM31CR71A226KE02" 1206_180 874.76,2788.63 r90 top value=22uF
C38 "Capacitor" 0603S 885,1277 r180 top value=56pF
C39 "Capacitor" 0603S 1212.76,2739.63 r180 top value=1uF
C40 "GCM188R71C105KA64D" 0603 2079.96,1386.31 r90 top value=1uF
C41 "EEE-FK1H101P" SM_RADIAL_F 1997,1903.45 r270 top value=100uF
C42 "CGA6P3X7S1H106K250AB" 1210_280 1987.74,1581.22 r270 top value=10uF
C43 "CGA6P3X7S1H106K250AB" 1210_280 1861.13,1580 r270 top value=10uF
C44 "CGA6P3X7S1H106K250AB" 1210_280 1931,2559 r0 top value=10uF
C45 "CGA5L3X7R1H105K160AB" 1206_180 1777,1330 r270 top value=1uF
C46 "CGA6P3X7S1H106K250AB" 1210_280 1668,1332 r270 top value=10uF
C47 "CGA6P3X7S1H106K250AB" 1210_280 2792,2435 r0 top value=10uF
C48 "CGA6P3X7S1H106K250AB" 1210_280 1754,2333 r0 top value=10uF
C49 "CGA6M3X7S2A475K200AB" 1210_220 2067,2398 r90 top value=4.7uF
C50 "CGA2B3X7R1H104M050BB" 0402 2483,1674 r270 top value=0.1uF
C51 "CGA3E3X7S2A104K080AB" 0603 2771,2339 r180 top value=0.1uF
C52 "CGA2B2X7R1H102K050BA" 0402 1172,1514 r270 top value=1000pF
C53 "CGA6M3X7S2A475K200AB" 1210_220 2506,2794 r180 top value=4.7uF
C54 "CGA6M3X7S2A475K200AB" 1210_220 2506,2654 r0 top value=4.7uF
C55 "CGA5L3X7S2A225K160AB" 1206_180 1536,2629 r0 top value=2.2uF
C56 "CGA5L2X7R2A104K160AA" 1206_180 1485.76,2268 r0 top value=0.1uF
C57 "Capacitor" 0603_HV 2542,1677 r270 top value=0.01uF
C58 "CGA2B2X7R1H102K050BA" 0402 2605,1679 r90 top value=1000pF
C59 "CGA3E3X7S2A104K080AB" 0603 2301,1539 r0 top value=0.1uF
C60 "CGA2B2X7R1H102K050BA" 0402 2691,1619 r270 top value=1000pF
C61 "EEE-FK2A220P" SM_RADIAL_F 1255,349 r90 top value=22uF
C62 "CGA6P3X7S1H106K250AB" 1210_280 2320,902 r90 top value=10uF
C63 "CGA6P3X7S1H106K250AB" 1210_280 2191,902 r90 top value=10uF
C64 "CGA6M3X7S2A475K200AB" 1210_220 1581,353 r180 top value=4.7uF
C65 "Capacitor" 0603_HV 2317,1676.5 r90 top value=2.2uF
C66 "CGA2B2X7R1H102K050BA" 0402 949.17,837 r180 top value=1000pF
C67 "CGA6M3X7S2A475K200AB" 1210_220 1935.12,1116.91 r270 top value=4.7uF
C68 "CGA6M3X7S2A475K200AB" 1210_220 2076.16,1117 r90 top value=4.7uF
C69 "CGA6M3X7S2A475K200AB" 1210_220 713.74,297 r270 top value=4.7uF
C70 "CGA5L2X7R2A104K160AA" 1206_180 1116,631.61 r0 top value=0.1uF
C71 "CGA2B3X7R1H104M050BB" 0402 2299,1322 r180 top value=0.1uF
C72 "CGA3E3X7S2A104K080AB" 0603 2413,896 r270 top value=0.1uF
C73 "Capacitor" 0603_HV 2535,1218 r90 top value=0.01uF
C74 "Capacitor" 0603_HV 2756,1449 r0 top value=2.2uF
C75 "CGA2B2X7R1H102K050BA" 0402 2744,1350 r90 top value=1000pF
C76 "CGA2B2X7R1H102K050BA" 0402 2716,1216 r270 top value=1000pF
C77 "CGA2B2X7R1H102K050BA" 0402 1054,1115 r180 top value=1000pF
C78 "CGA3E2X7R2A223K080AA" 0603 773,657 r270 top value=0.022uF
C79 "CGA5L2X7R2A105K160AA" 1206_180 1916,2769 r270 top value=1uF
C80 "CGA3E3X7S2A104K080AB" 0603 686.96,2831 r180 top value=0.1uF
C81 "CGA2B3X7R1H104M050BB" 0402 207.96,2228.67 r180 top value=0.1uF
C82 "GRM188R72A103KA01D" 0603 884,1028 r180 top value=0.01uF
C84 "GRM188R72A103KA01D" 0603 888.15,1198 r180 top value=0.01uF
C85 "CGA5L2X7R2A105K160AA" 1206_180 2050,918 r90 top value=1uF
C86 "CGA2B3X7R1H104M050BB" 0402 2302,1273 r180 top value=0.1uF
C87 "CGA2B3X7R1H104M050BB" 0402 2430,1674 r90 top value=0.1uF
C88 "CGA6M3X7S2A475K200AB" 1210_220 1580,483 r180 top value=4.7uF
C89 "GCM31CR71A226KE02" 1206_180 236.07,1088 r180 top value=22uF
C90 "Capacitor" 0603 1346,1179.3 r90 top value=1000pF
D2 "PDS3100Q-13" POWERDI5 2311,2689 r90 top value=100V
D3 "SZMM3Z3V3ST1G" SOD-323 2289,1431 r180 top value=3.3V
D4 "FSV8100V" TO-277A 1608.57,671.94 r90 top value=100V
Designator11 "Comment" 3mmpad 3090,1659 r180 bottom
Designator12 "Comment" 3mmpad 3089,1852 r180 bottom
Designator13 "Comment" 3mmpad 3087,1464.56 r180 bottom
Designator14 "Comment" 3mmpad 1418.83,1342 r180 bottom
Designator15 "Comment" 3mmpad 1418,1490.38 r180 bottom
Designator16 "Comment" 3mmpad 1417,1626.19 r180 bottom
Designator17 "Comment" 3mmpad 1357.92,1700.69 r180 bottom
Designator18 "Comment" 3mmpad 1231,1700.69 r180 bottom
Designator19 "Comment" 3mmpad 1121.96,1699 r180 bottom
Designator20 "Comment" 3mmpad 996,1700.02 r180 bottom
Designator21 "Comment" 3mmpad 864,1700.02 r180 bottom
Designator22 "Comment" 3mmpad 806.26,1630 r180 bottom
Designator23 "Comment" 3mmpad 809.14,1478.5 r180 bottom
Designator24 "Comment" 3mmpad 808.42,1343.32 r180 bottom
Designator25 "Comment" 3mmpad 810,1221 r180 bottom
Designator26 "Comment" 3mmpad 810.69,1082 r180 bottom
Designator27 "Comment" 3mmpad 811.52,960 r180 bottom
Designator28 "Comment" 3mmpad 811,846 r180 bottom
Designator29 "Comment" 3mmpad 869.45,788 r180 bottom
Designator30 "Comment" 3mmpad 1002,788 r180 bottom
Designator31 "Comment" 3mmpad 1133,787.2 r180 bottom
Designator32 "Comment" 3mmpad 1255.46,787.2 r180 bottom
Designator33 "Comment" 3mmpad 1371,788 r180 bottom
Designator34 "Comment" 3mmpad 1422,843 r180 bottom
Designator35 "Comment" 3mmpad 1423,955.7 r180 bottom
Designator36 "Comment" 3mmpad 1422,1083 r180 bottom
Designator37 "Comment" 3mmpad 1420.48,1210 r180 bottom
Designator38 "Comment" 3mmpad 3088,54 r180 bottom
Designator39 "Comment" 3mmpad 3085,252 r180 bottom
Designator40 "Comment" 3mmpad 3085,456 r180 bottom
Designator41 "Comment" 3mmpad 3087,654.98 r180 bottom
Designator42 "Comment" 3mmpad 3087,868 r180 bottom
Designator43 "Comment" 3mmpad 3085,1071.26 r180 bottom
Designator44 "Comment" 3mmpad 3086,1271.24 r180 bottom
Designator45 "Comment" 3mmpad 3089,2046.76 r180 bottom
Designator46 "Comment" 3mmpad 3087,2246 r180 bottom
Designator47 "Comment" 3mmpad 3088,2446 r180 bottom
Designator48 "Comment" 3mmpad 3085,2649.81 r180 bottom
Designator49 "Comment" 3mmpad 3088,2845 r180 bottom
Designator50 "Comment" 3mmpad 2982,2945 r180 bottom
Designator51 "Comment" 3mmpad 2774,2942 r180 bottom
Designator52 "Comment" 3mmpad 2568.87,2939 r180 bottom
Designator53 "Comment" 3mmpad 2350,2937 r180 bottom
Designator54 "Comment" 3mmpad 2150,2937 r180 bottom
Designator55 "Comment" 3mmpad 1950,2937 r180 bottom
Designator56 "Comment" 3mmpad 1750,2937 r180 bottom
Designator57 "Comment" 3mmpad 1550,2937 r180 bottom
Designator58 "Comment" 3mmpad 1350,2937 r180 bottom
Designator59 "Comment" 3mmpad 1150,2937 r180 bottom
Designator60 "Comment" 3mmpad 950,2937 r180 bottom
Designator61 "Comment" 3mmpad 750,2937 r180 bottom
Designator62 "Comment" 3mmpad 550,2937 r180 bottom
Designator63 "Comment" 3mmpad 350,2937 r180 bottom
Designator64 "Comment" 3mmpad 152,2939 r180 bottom
Designator65 "Comment" 3mmpad 61,2843 r180 bottom
Designator66 "Comment" 3mmpad 62,2649.81 r180 bottom
Designator67 "Comment" 3mmpad 59,2449 r180 bottom
Designator68 "Comment" 3mmpad 61,2237 r180 bottom
Designator69 "Comment" 3mmpad 60,2036 r180 bottom
Designator70 "Comment" 3mmpad 57,1833 r180 bottom
Designator71 "Comment" 3mmpad 58,1632 r180 bottom
Designator72 "Comment" 3mmpad 59,1437 r180 bottom
Designator73 "Comment" 3mmpad 58,1249 r180 bottom
Designator74 "Comment" 3mmpad 59,1067 r180 bottom
Designator75 "Comment" 3mmpad 59,883 r180 bottom
Designator76 "Comment" 3mmpad 60,702 r180 bottom
Designator77 "Comment" 3mmpad 60,523 r180 bottom
Designator78 "Comment" 3mmpad 56,340 r180 bottom
Designator79 "Comment" 3mmpad 55,146 r180 bottom
Designator80 "Comment" 3mmpad 160,49 r180 bottom
Designator81 "Comment" 3mmpad 373,48 r180 bottom
Designator82 "Comment" 3mmpad 580,50 r180 bottom
Designator83 "Comment" 3mmpad 791.94,49 r180 bottom
Designator84 "Comment" 3mmpad 995,50 r180 bottom
Designator85 "Comment" 3mmpad 1200,50 r180 bottom
Designator86 "Comment" 3mmpad 1400,50 r180 bottom
Designator87 "Comment" 3mmpad 1600,50 r180 bottom
Designator88 "Comment" 3mmpad 1800,50 r180 bottom
Designator89 "Comment" 3mmpad 2000,50 r180 bottom
Designator90 "Comment" 3mmpad 2200,50 r180 bottom
Designator91 "Comment" 3mmpad 2400,50 r180 bottom
Designator92 "Comment" 3mmpad 2600,50 r180 bottom
Designator93 "Comment" 3mmpad 2800,50 r180 bottom
FID1 "Fiducial" Fiducial10-20 2943,2522 r0 top
FID2 "Fiducial" Fiducial10-20 478,147 r0 top
FID3 "Fiducial" Fiducial10-20 2657,153 r0 top
J1 "Header_5x2" Samtec_FTSH-105-01-x-DV 309.58,1595.64 r0 top
J2 "TSM-107-01-L-DV" Samtec_TSM-107-01-x-DV 1137,1266 r180 bottom
L1 "Inductor_Iron" NLCV32 391,955 r270 top value=1uH
L2 "INDUCTOR_COUPLED_12_43" SIMDAD_1812 572,1332 r90 top value=100uH
L3 "FDSD0420D-4R7M" FDSD0420 1025.76,2787.63 r270 top value=4.7uH
L4 "XAL7070-332MEB" XAL7070 1616,1927 r90 top value=3.3uH
L5 "B82477D4333M000" B82477D4 2428,2315 r180 top value=15uH
L6 "IHLP1616BZER4R7M11" IHLP-1616BZ 1740,2774 r180 top value=4.7uH
L7 "782853221" 0805_HV 1396,1818 r90 top value="220 ohm"
L8 "XAL1510-153MEB" XAL1510 2161.82,459 r270 top value=15uH
L9 "CLF10060NIT-150M-D" CLF10060NI-D 1611,1005.8 r90 top value=15uH
L10 "IHLP1616BZER4R7M11" IHLP-1616BZ 915,306.04 r180 top value=4.7uH
L11 "782853221" 0805_HV 973.86,689 r270 top value="220 ohm"
L12 "782853221" 0805_HV 873,957.53 r0 top value="220 ohm"
L13 "782853221" 0805_HV 1367.46,1485 r0 top value="220 ohm"
L14 "782853221" 0805_HV 854,1105 r180 top value="220 ohm"
L15 "28F0181-1SR-10" 28F0181 1377,1343.32 r0 top value="115 ohm"
LBL1 "THT-14-423-10" Label_650x200 2173,260 r180 bottom
Logo1 "CE Mark" CE_Mark_5mm 1430,291 r180 bottom
Logo2 "Texas Instruments" TI_Stacked_Overlay_Small 2251,968 r180 bottom
Logo3 "FCC disclaimer" FCC_disclaimer 1431,3009 r0 top
Logo4 "WEEE logo" WEEE_Minimum 807,450 r180 bottom
Logo5 "CAUTION.  READ USER GUIDE BEFORE USE" IEC_Caution_Small 2329.62,2539 r180 bottom
LOGO6 "CAUTION HOT SURFACE" IEC_HotSurface_Small 1805.39,2121 r180 bottom
Q1 "NVMFS5C604NLT1G" TRANS_DFN5 1644,1612.67 r90 top value=60V
Q2 "NVTFS5116PLTAG" Power_WDFN-8 1495,2473 r270 top value=-60V
Q3 "STL8N10LF3" PowerFLAT5x6_R 2468,1924 r180 top value=100V
Q4 "NVTFS5116PLTAG" Power_WDFN-8 930,503 r90 top value=-60V
Q6 "MOSFET_N_D56789G4S123" PowerDI3333-8 652.62,682.06 r90 top value=100V
Q7 "BUK9611-80E,118" DDPAK 2776,796.45 r270 top value=80V
R1 "RMCF0402JT100R" 0402 212.76,1940.63 r0 top value=100
R2 "RMCF0402FT10K0" 0402 212.76,1894.63 r0 top value=10.0k
R3 "RMCF0402FT10K0" 0402 673.05,1646 r0 top value=10.0k
R4 "RMCF0402FT33R0" 0402 212.76,1850.63 r180 top value=33.0
R5 "RMCF0402FT33R0" 0402 511.93,1646 r0 top value=33.0
R6 "RMCF0402FT33R0" 0402 511.93,1596 r0 top value=33.0
R7 "RMCF0402FT33R0" 0402 513.9,1548.12 r0 top value=33.0
R8 "RMCF0402FT10K0" 0402 674.05,1596 r0 top value=10.0k
R9 "Resistor" 0603 1269,2063.63 r180 top value=51
R10 "Resistor" 0402 1316.76,2232.69 r90 top value=10k
R13 "RMCF0402FT10K0" 0402 646.5,1548.12 r0 top value=10.0k
R14 "CRCW0402100KFKED" 0402 2302,1224 r180 top value=100k
R16 "ERA-2AEB4871X" 0402 832,1811.81 r270 top value=4.87k
R17 "Resistor" 0402 1098.34,2385.27 r0 top value=0
R18 "Resistor" 0402 308,828 r0 top value=10k
R19 "CSRN2512FTR100" 2512 1807.98,2178 r180 top value=0.1
R20 "Thermistor" 0603_HV 2571.49,177.33 r90 top value=100k
R21 "Resistor" 0603S 1354.76,2693.63 r0 top value=2.20k
R22 "Resistor" 0603_HV 1510.76,2749.9 r0 top value=100k
R23 "Resistor" 1206 639,1464 r180 top value=60.4
R24 "Resistor" 0402S 1210.76,2804.63 r270 top value=0.47
R25 "Resistor" 1206 635,1200 r0 top value=60.4
R26 "RMCF0402FT10K0" 0402 485.76,2647.63 r270 top value=10.0k
R28 "RMCF0402FT10K0" 0402 207.96,2278.67 r180 top value=10.0k
R29 "Resistor" 1206 2106,2809.57 r180 top value=0.1
R30 "Resistor" 0603_HV 2831.31,1874 r270 top value=0
R31 "Resistor" 0603 550.76,2830.63 r180 top value=10k
R32 "Resistor" 0603_HV 2181,2694.57 r90 top value=100k
R33 "Resistor" 0603_HV 2116,2694.57 r90 top value=10.0
R34 "Resistor" 0603_HV 2046,2694.57 r90 top value=10.0
R35 "CRCW06035K90FKEA" 0603 549.76,2777.63 r0 top value=5.90k
R36 "CRCW040210R0FKED" 0402 2756,1619 r270 top value=10.0
R37 "Resistor" 0603_HV 2111,2564 r90 top value=2.20k
R38 "CRA2512-FZ-R030ELF" 2512 2711.31,1884 r270 top value=0.03
R39 "CRCW0402100KFKED" 0402 2306,1484 r0 top value=100k
R40 "Resistor" 0603_HV 1359.76,2638.63 r180 top value=10.0
R41 "Resistor" 0603_HV 1043,470 r90 top value=10.0
R42 "CRCW25121R20FKEG" 2512 1585,208 r180 top value=1.20
R43 "CRCW0402100KFKED" 0402 2300,1371 r180 top value=100k
R44 "RMCF0402FT10K0" 0402 1275,2155 r0 top value=10.0k
R45 "RMCF0402FT10K0" 0402 1101.76,2163.63 r0 top value=10.0k
R46 "Resistor" 0603 1032,1815 r0 top value=10k
R47 "Resistor" 0603_HV 2257,1676.5 r270 top value=100k
R48 "Resistor" 1206 1934,919 r270 top value=0.1
R49 "Resistor" 0603_HV 2907,1217 r90 top value=0
R50 "Resistor" 0603_HV 2663,1218 r270 top value=100k
R51 "Resistor" 0603_HV 2601,1219 r270 top value=10.0
R52 "Resistor" 0603_HV 2472,1217 r270 top value=10.0
R53 "Resistor" 0603_HV 2844,1219 r90 top value=10.0
R54 "Resistor" 0603 835,1512.05 r180 top value=10k
R55 "Resistor" 0603_HV 2772,1217 r90 top value=2.20k
R56 "CRE2512-FZ-R008E-2" CRE2512-R5_R9 2426,1077 r0 top value=0.008
R57 "CRCW0603100KFKEA" 0603 697.67,526.56 r0 top value=100k
R59 "RMCF0402FT33R0" 0402 564.23,1813.07 r270 top value=33.0
R60 "RMCF0402FT33R0" 0402 614.23,1813.07 r270 top value=33.0
R61 "RMCF0402FT33R0" 0402 214.76,2532.63 r0 top value=33.0
R62 "RMCF0402FT33R0" 0402 214.76,2484.63 r0 top value=33.0
R63 "RMCF0402FT33R0" 0402 213.76,2433.63 r0 top value=33.0
R66 "Resistor" 0603 804,506 r270 top value=10k
R70 "CRCW0402100KFKED" 0402 2377,1675 r270 top value=100k
R71 "RMCF0402FT33R0" 0402 720.76,2649.63 r270 top value=33.0
R72 "RMCF0402FT10K0" 0402 473,465 r270 top value=10.0k
U1 "MSP432E401YTPDTR" PDT0128A 663.39,2237.85 r0 top
U2 "TPS61240" DRV0006A 246,910.28 r0 top
U3 "TCAN1042HVDRQ1" D0008A_L 303,1311 r0 top
U4 "LM5360x_DSX" DSX0010A 1360,2808.63 r0 top
U5 "TI-TPD2E007-SC70_DCK-3" DCK0003A_N 486.76,1144.88 r270 top
U6 "TPS92682QRHMQ1" RHM0032A 2527,1439.76 r0 top
U7 "LM74700QDBVTQ1" DBV0006A_N 1950.96,1392.31 r180 top
Y1 "Xtal" NDK_NX5032GA 1235.76,2461.92 r270 top
ZZ1 "This Assembly Note is for PCB labels only" AssemblyNoteLabel -674,3847 r0 top
ZZ2 "These assemblies are ESD sensitive, ESD precautions shall be observed." AssemblyNote -674,3738.11 r0 top
ZZ3 "These assemblies must be clean and free from flux and all contaminants. Use of no clean flux is not acceptable." AssemblyNote -674,3649.56 r0 top
ZZ4 "These assemblies must comply with workmanship standards IPC-A-610 Class 2, unless otherwise specified." AssemblyNote -674,3561 r0 top

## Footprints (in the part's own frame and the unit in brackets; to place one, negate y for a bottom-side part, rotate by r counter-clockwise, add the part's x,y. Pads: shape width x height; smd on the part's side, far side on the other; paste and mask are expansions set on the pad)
3mmpad [mm]
  round 1.5 smd paste+0 mask+0.102: 1(0,0)
  round 1.5 on Bottom Solder paste+0 mask+0.102: 1(0,0)
28F0181 [mm] "SMD, 2-Leads, Body 8.74x4.65mm"
  rect 3.3x4.06 smd: 1(-4.015,0) 2(4.015,0)
  silkscreen extent -4.37,-2.32 4.37,2.32, body extent -4.76,-2.32 4.77,2.32, height 3.05
0402 [mm] "0402 from SM-752 data"
  rect 0.8x0.6 smd: 1(-0.6,0) 2(0.6,0)
  silkscreen extent -1.22,-0.52 1.22,0.52, body extent -0.55,-0.3 0.55,0.3, height 0.6
0402S [mil] "Based on C0402S footprint from PADS legacy"
  rect 15x24 smd: 1(-20,0) 2(20,0)
  body extent -22,-12 22,12, height 24
0603 [mm] "0603 from SM-752 data"
  rect 1x0.95 smd: 1(-0.8,0) 2(0.8,0)
  silkscreen extent -1.52,-0.69 1.52,0.69, body extent -0.87,-0.47 0.87,0.47, height 1
0603_HV [mil] "Ernesto recommended land pattern.  26 mil between pads."
  rect 30x30 smd: 1(-28,0) 2(28,0)
  silkscreen extent -52,-24 52,24, body extent -34,-19 34,19, height 39
0603S [mil]
  rect 20x35 smd: 1(-30,0) 2(30,0)
  body extent -34,-19 34,19, height 39
0805_HV [mil] "0805 with 30mil clearance between pads"
  rect 50x63 smd: 1(-40,0) 2(40,0)
  silkscreen extent -74,-40 74,40, body extent -43,-29 43,29, height 57
1206 [mm] "1206 from SM-752 data"
  rect 1.3x1.85 smd: 1(-1.45,0) 2(1.45,0)
  silkscreen extent -2.4,-1.21 2.4,1.21, body extent -1.7,-0.9 1.7,0.9, height 1.35
1206_180 [mm] "1206_180"
  rect 1.1x1.6 smd: 1(-1.7,0) 2(1.7,0)
  silkscreen extent -0.9,-1 0.9,1, body extent -1.75,-0.95 1.75,0.95, height 1.8
1210_220 [mm] "1210"
  rect 1.3x2.7 smd: 1(-1.45,0) 2(1.45,0)
  silkscreen extent -2.32,-1.57 2.32,1.57, body extent -1.7,-1.35 1.7,1.35, height 2.2
1210_280 [mm] "SMD, 2-Leads, Body 3.6x2.8mm, Height 2.8mm"
  rect 1.1x2.2 smd: 1(-1.65,0) 2(1.65,0)
  silkscreen extent -0.84,-1.4 0.84,1.4, body extent -1.8,-1.4 1.8,1.4, height 2.8
2512 [mm] "Chip Resistor, Body 6.3x3.2mm, IPC Medium Density"
  rect 1.3x3.4 smd: 1(-2.95,0) 2(2.95,0)
  silkscreen extent -1.9,-1.6 1.9,1.6, body extent -3.22,-1.67 3.22,1.67, height 0.71
AssemblyNote [mil] "Assembly Note"
AssemblyNoteLabel [mil] "Assembly Note for PCB Labels"
B82477D4 [mm] "SMD, 4-Leads, Body 12.5x12.5mm"
  rect 3.1x2.3 smd: 1(-4.95,1.75) 2(-4.95,-1.75) 3(4.95,-1.75) 4(4.95,1.75)
  silkscreen extent -6.6,-6.25 6.25,6.25, body extent -6.25,-6.25 6.25,6.25, height 8.5
CE_Mark_5mm [mil] "Minimum text height for CE Mark"
  silkscreen extent -138,-98 138,98
CLF10060NI-D [mm] "SMD, 2-Leads, Body 10.1x10mm"
  rrect3% 3.3x3.7 smd: 1(-3.95,0) 2(3.95,0)
  body extent -5.2,-5.15 5.2,5.15, height 6.31
CRE2512-R5_R9 [mm] "SMD, 2-Leads, Body 6.45x3.35mm, Pitch 6.2mm"
  rect 2.1x4 smd: 1(-3.1,0) 2(3.1,0)
  silkscreen extent -1.6,-1.78 1.6,1.78, body extent -3.32,-1.77 3.32,1.77, height 0.9
D0008A_L [mm] "SOIC, 8-Leads, Body 4.9x3.9mm, Pitch 1.27mm, IPC High Density"
  oval 1.25x0.55 smd: 1(-2.625,1.905) 2(-2.625,0.635) 3(-2.625,-0.635) 4(-2.625,-1.905) 5(2.625,-1.905) 6(2.625,-0.635) 7(2.625,0.635) 8(2.625,1.905)
  silkscreen extent -3.1,-2.5 0.9,2.5, body extent -3,-2.45 3,2.45, height 1.63
DBV0006A_N [mm] "SOT23, 6-Leads, Body 2.9x1.6mm, Pitch 0.95mm, Lead Span 2.8mm, IPC Medium Density"
  rrect17% 1x0.6 smd: 1(-1.375,0.95) 2(-1.375,0) 3(-1.375,-0.95) 4(1.375,-0.95) 5(1.375,0) 6(1.375,0.95)
  silkscreen extent -1.68,-1.55 0.5,1.55, body extent -1.42,-1.46 1.42,1.46, height 1.12
DCK0003A_N [mm] "SOT23, 3-Leads, Body 2.0x1.25mm, Pitch 0.65mm, Lead Span 2.1mm, IPC Medium Density"
  rrect25% 0.85x0.4 smd: 1(-1.125,0.65) 2(-1.125,-0.65) 3(1.125,0)
  silkscreen extent -1.02,-1.1 0.7,1.53, body extent -1.06,-1 1.06,1, height 1.1
DDPAK [mil] "D2-PAK, 3-Pads, Body 9.7x10.4mm (max), TO-263AB, using Vishay Silionix recommended pad sizes"
  rrect8% 135x49.49 smd: 1(-246.06,100) 3(-246.06,-100)
  rrect1% 355x420 smd paste-181.1: 2(155.51,0)
  body extent -295,-202 324,202, height 180
DRV0006A [mm] "SON, 6-Leads, Body 2x2mm, Pitch 0.65mm, Thermal Pad 1.6x1mm, TI Recommended"
  rrect33% 0.45x0.3 smd: 1(-0.975,0.65) 2(-0.975,0) 3(-0.975,-0.65) 4(0.975,-0.65) 5(0.975,0) 6(0.975,0.65)
  rrect14% 1x0.7 on Top Paste: 7(0,-0.45) 7(0,0.45)
  rrect10% 1x1.6 smd paste-0.5: 7(0,0)
  silkscreen extent -1.05,-1.2 1.05,1.2, body extent -1.05,-1.05 1.05,1.05, height 0.81
DSX0010A [mm] "SON, 10-Leads, Body 3x3 mm, Pitch 0.5mm"
  rrect40% 0.6x0.25 smd: 1(-1.4,1) 2(-1.4,0.5) 3(-1.4,0) 4(-1.4,-0.5) 5(-1.4,-1) 6(1.4,-1) 7(1.4,-0.5) 8(1.4,0) 9(1.4,0.5) 10(1.4,1)
  rrect40% 0.25x0.34 on Top Paste: 11(-0.25,-1.53) 11(-0.25,1.53) 11(0.25,-1.53) 11(0.25,1.53)
  rrect9% 1.5x1.06 on Top Paste: 11(0,-0.63) 11(0,0.63)
  rrect12% 1.65x2.4 smd paste-1 mask-2: 11(0,0)
  Top Layer region: -0.775,-1.2 -0.375,-1.2 -0.375,-1.65 -0.371,-1.669 -0.36,-1.685 -0.344,-1.696 -0.325,-1.7 -0.325,-1.7 -0.325,-1.7 -0.175,-1.7 -0.175,-1.7 -0.156,-1.696 -0.14,-1.685 -0.129,-1.669 -0.125,-1.65 -0.125,-1.65 -0.125,-1.65 -0.125,-1.2 0.125,-1.2 0.125,-1.65 0.129,-1.669 0.14,-1.685 0.156,-1.696 0.175,-1.7 0.175,-1.7 0.175,-1.7 0.325,-1.7 0.325,-1.7 0.344,-1.696 0.36,-1.685 0.371,-1.669 0.375,-1.65 0.375,-1.65 0.375,-1.2 0.775,-1.2 0.794,-1.196 0.81,-1.185 0.821,-1.169 0.825,-1.15 0.825,-1.15 0.825,1.15 0.821,1.169 0.81,1.185 0.794,1.196 0.775,1.2 0.775,1.2 0.375,1.2 0.375,1.65 0.371,1.669 0.36,1.685 0.344,1.696 0.325,1.7 0.325,1.7 0.175,1.7 0.156,1.696 0.14,1.685 0.129,1.669 0.125,1.65 0.125,1.65 0.125,1.2 -0.125,1.2 -0.125,1.65 -0.125,1.65 -0.129,1.669 -0.14,1.685 -0.156,1.696 -0.175,1.7 -0.175,1.7 -0.325,1.7 -0.344,1.696 -0.36,1.685 -0.371,1.669 -0.375,1.65 -0.375,1.65 -0.375,1.2 -0.775,1.2 -0.794,1.196 -0.81,1.185 -0.821,1.169 -0.825,1.15 -0.825,1.15 -0.825,-1.15 -0.821,-1.169 -0.81,-1.185 -0.794,-1.196 -0.775,-1.2
  silkscreen extent -1.63,-1.63 1.63,1.63, body extent -1.5,-1.5 1.5,1.5, height 0.8
FCC_disclaimer [mil]
FDSD0420 [mm] "SMD, 2-Leads, Body 4.2x4.2mm"
  rect 1.4x2.4 smd: 1(-1.6,0) 2(1.6,0)
  silkscreen extent -2.2,-2.2 2.2,2.2, body extent -2.1,-2.1 2.1,2.1, height 2
Fiducial10-20 [mm]
  round 1 smd mask+0.5: 1(0,0)
  Top Layer keep-out circle w1.178: c0,0 r0.5
IEC_Caution_Small [mil]
  silkscreen extent -107,-93 107,92
IEC_HotSurface_Small [mil]
  silkscreen extent -107,-93 107,92
IHLP-1616BZ [mm] "Vishay Dale recommended land pattern."
  rect 1.65x2.3 smd: 1(-1.65,0) 2(1.65,0)
  silkscreen extent -2.45,-2.25 2.45,2.25, body extent -2.35,-2.16 2.35,2.16, height 2
Label_650x200 [mil] "Thermal Transfer Label"
  round 1 on Mech14: 0(0,0)
  silkscreen extent -325,-100 325,100, body extent -325,-100 325,100, height 1
NDK_NX5032GA [mm] "SMD, 2-Leads Body 5x3.2mm"
  rect 2x2.4 smd: 1(-2,0) 2(2,0)
  silkscreen extent -2.6,-1.7 2.6,1.7, body extent -2.6,-1.7 2.6,1.7, height 1.5
NLCV32 [mm] "TDK"
  rect 1.2x2 smd: 1(-1.6,0) 2(1.6,0)
  silkscreen extent -0.9,-1.4 0.9,1.4, body extent -1.7,-1.35 1.7,1.35, height 2.4
PDT0128A [mm] "Thin QFP, 128-Leads, Body 14x14mm, Pitch 0.4mm"
  oval 1.4x0.2 smd: 1(-7.7,6.2) 2(-7.7,5.8) 3(-7.7,5.4) 4(-7.7,5) 5(-7.7,4.6) 6(-7.7,4.2) 7(-7.7,3.8) 8(-7.7,3.4) 9(-7.7,3) 10(-7.7,2.6) 11(-7.7,2.2) 12(-7.7,1.8) 13(-7.7,1.4) 14(-7.7,1) 15(-7.7,0.6) 16(-7.7,0.2) 17(-7.7,-0.2) 18(-7.7,-0.6) 19(-7.7,-1) 20(-7.7,-1.4) 21(-7.7,-1.8) 22(-7.7,-2.2) 23(-7.7,-2.6) 24(-7.7,-3) 25(-7.7,-3.4) 26(-7.7,-3.8) 27(-7.7,-4.2) 28(-7.7,-4.6) 29(-7.7,-5) 30(-7.7,-5.4) 31(-7.7,-5.8) 32(-7.7,-6.2) 65(7.7,-6.2) 66(7.7,-5.8) 67(7.7,-5.4) 68(7.7,-5) 69(7.7,-4.6) 70(7.7,-4.2) 71(7.7,-3.8) 72(7.7,-3.4) 73(7.7,-3) 74(7.7,-2.6) 75(7.7,-2.2) 76(7.7,-1.8) 77(7.7,-1.4) 78(7.7,-1) 79(7.7,-0.6) 80(7.7,-0.2) 81(7.7,0.2) 82(7.7,0.6) 83(7.7,1) 84(7.7,1.4) 85(7.7,1.8) 86(7.7,2.2) 87(7.7,2.6) 88(7.7,3) 89(7.7,3.4) 90(7.7,3.8) 91(7.7,4.2) 92(7.7,4.6) 93(7.7,5) 94(7.7,5.4) 95(7.7,5.8) 96(7.7,6.2)
  oval 0.2x1.4 smd: 33(-6.2,-7.7) 34(-5.8,-7.7) 35(-5.4,-7.7) 36(-5,-7.7) 37(-4.6,-7.7) 38(-4.2,-7.7) 39(-3.8,-7.7) 40(-3.4,-7.7) 41(-3,-7.7) 42(-2.6,-7.7) 43(-2.2,-7.7) 44(-1.8,-7.7) 45(-1.4,-7.7) 46(-1,-7.7) 47(-0.6,-7.7) 48(-0.2,-7.7) 49(0.2,-7.7) 50(0.6,-7.7) 51(1,-7.7) 52(1.4,-7.7) 53(1.8,-7.7) 54(2.2,-7.7) 55(2.6,-7.7) 56(3,-7.7) 57(3.4,-7.7) 58(3.8,-7.7) 59(4.2,-7.7) 60(4.6,-7.7) 61(5,-7.7) 62(5.4,-7.7) 63(5.8,-7.7) 64(6.2,-7.7) 97(6.2,7.7) 98(5.8,7.7) 99(5.4,7.7) 100(5,7.7) 101(4.6,7.7) 102(4.2,7.7) 103(3.8,7.7) 104(3.4,7.7) 105(3,7.7) 106(2.6,7.7) 107(2.2,7.7) 108(1.8,7.7) 109(1.4,7.7) 110(1,7.7) 111(0.6,7.7) 112(0.2,7.7) 113(-0.2,7.7) 114(-0.6,7.7) 115(-1,7.7) 116(-1.4,7.7) 117(-1.8,7.7) 118(-2.2,7.7) 119(-2.6,7.7) 120(-3,7.7) 121(-3.4,7.7) 122(-3.8,7.7) 123(-4.2,7.7) 124(-4.6,7.7) 125(-5,7.7) 126(-5.4,7.7) 127(-5.8,7.7) 128(-6.2,7.7)
  silkscreen extent -7.7,-6.3 6.3,6.99, body extent -8,-8 8,8, height 1.07
Power_WDFN-8 [mm] "SMD, 8-Leads, Body 3.3x3.3mm, Pitch 0.65mm"
  rect 0.66x0.42 smd: 1(-1.47,0.975) 2(-1.47,0.325) 3(-1.47,-0.325) 4(-1.47,-0.975) 5(1.47,-0.975) 6(1.47,-0.325) 7(1.47,0.325) 8(1.47,0.975) 9(0,0)
  Top Layer region: 0.25,1.73 -0.32,1.73 -0.32,1.185 -0.5,1.185 -0.5,-1.185 -0.32,-1.185 -0.32,-1.73 0.25,-1.73 0.25,-1.185 1.33,-1.185 1.33,1.185 0.25,1.185
  silkscreen extent -1.9,-1.65 1.65,1.75, body extent -1.65,-1.65 1.65,1.65, height 0.81
POWERDI5 [mm] "Diodes Inc recommended land pattern, ap02001.pdf rev 60"
  rect 1.4x1.39 smd: 1(-1.991,0.92) 2(-1.991,-0.92)
  rect 4.86x3.36 smd: 3(1.991,0)
  silkscreen extent -1.7,-2.1 3.8,2.1, body extent -2.27,-2.03 4.33,2.03, height 1.17
PowerDI3333-8 [mm] "SMD, 8-Leads, Body 3.3x3.3mm, Pitch 0.65mm"
  rect 0.7x0.42 smd: 1(-1.5,0.975) 2(-1.5,0.325) 3(-1.5,-0.325) 4(-1.5,-0.975) 5(1.5,-0.975) 6(1.5,-0.325) 7(1.5,0.325) 8(1.5,0.975)
  rect 1.55x2.37 smd: 9(0.375,0)
  silkscreen extent -1.68,-1.68 1.68,1.9, body extent -1.68,-1.68 1.68,1.68, height 0.86
PowerFLAT5x6_R [mm] "SMD, 8-Leads, Body 6.15x5.2mm, Pitch 1.27mm"
  rect 1.25x0.65 smd: 1(-2.675,1.905) 2(-2.675,0.635) 3(-2.675,-0.635) 4(-2.675,-1.905) 5(2.675,-1.905) 6(2.675,-0.635) 7(2.675,0.635) 8(2.675,1.905) 9(0,0)
  Top Layer region: -0.96,2.7 -0.96,2.225 -1.15,2.225 -1.15,-2.225 -0.96,-2.225 -0.96,-2.7 -0.16,-2.7 -0.16,-2.225 1.49,-2.225 1.49,-2.7 2.29,-2.7 2.29,-2.225 2.75,-2.225 2.75,2.225 2.29,2.225 2.29,2.7 1.49,2.7 1.49,2.225 -0.16,2.225 -0.16,2.7
  silkscreen extent -3.18,-2.7 3.18,2.9, body extent -3.17,-2.7 3.17,2.7, height 1.01
RHM0032A [mm] "VQFNP-32"
  rrect40% 0.6x0.25 smd: 1(-2.4,1.75) 2(-2.4,1.25) 3(-2.4,0.75) 4(-2.4,0.25) 5(-2.4,-0.25) 6(-2.4,-0.75) 7(-2.4,-1.25) 8(-2.4,-1.75) 17(2.4,-1.75) 18(2.4,-1.25) 19(2.4,-0.75) 20(2.4,-0.25) 21(2.4,0.25) 22(2.4,0.75) 23(2.4,1.25) 24(2.4,1.75)
  rrect40% 0.25x0.6 smd: 9(-1.75,-2.4) 10(-1.25,-2.4) 11(-0.75,-2.4) 12(-0.25,-2.4) 13(0.25,-2.4) 14(0.75,-2.4) 15(1.25,-2.4) 16(1.75,-2.4) 25(1.75,2.4) 26(1.25,2.4) 27(0.75,2.4) 28(0.25,2.4) 29(-0.25,2.4) 30(-0.75,2.4) 31(-1.25,2.4) 32(-1.75,2.4)
  rrect3% 3.7x3.7 smd paste-2: 33(0,0)
  body extent -2.5,-2.5 2.5,2.5, height 0.85
Samtec_FTSH-105-01-x-DV [mm] "Header, 1.27mm, 5x2, SMT"
  rect 2.79x0.74 smd: 1(-2.035,2.54) 2(2.035,2.54) 3(-2.035,1.27) 4(2.035,1.27) 5(-2.035,0) 6(2.035,0) 7(-2.035,-1.27) 8(2.035,-1.27) 9(-2.035,-2.54) 10(2.035,-2.54)
  silkscreen extent -3.73,-3.48 3.73,3.48, body extent -2.92,-3.17 2.92,3.18, height 5.98
Samtec_TSM-107-01-x-DV [mm] "Header, 2.54mm, 7x2, SMT"
  rect 3.68x1.27 smd: 1(-2.475,7.62) 2(2.475,7.62) 3(-2.475,5.08) 4(2.475,5.08) 5(-2.475,2.54) 6(2.475,2.54) 7(-2.475,0) 8(2.475,0) 9(-2.475,-2.54) 10(2.475,-2.54) 11(-2.475,-5.08) 12(2.475,-5.08) 13(-2.475,-7.62) 14(2.475,-7.62)
  silkscreen extent -1.65,-8.89 1.65,9.03, body extent -3.85,-8.89 3.85,8.89, height 9.65
SIMDAD_1812 [mm] "EPCOS"
  rect 1.7x1.85 smd: 1(-1.15,2.025) 2(-1.15,-2.025) 3(1.15,-2.025) 4(1.15,2.025)
  silkscreen extent -2,-0.8 1.75,0.9, body extent -1.75,-2.6 1.75,2.6, height 3.01
SM_RADIAL_F [mm] "8 x 10.2mm:  Panasonic F"
  rect 4x2 smd: 1(-3.55,0) 2(3.55,0)
  silkscreen extent -4.25,-4.25 4.25,4.25, body extent -4.25,-4.25 4.25,4.25, height 10.5
SOD-323 [mm] "NXP recommended land pattern"
  rect 0.6x0.6 smd paste-0.05: 1(-1.1,0) 2(1.1,0)
  silkscreen extent -2.06,-0.86 1.53,0.86, body extent -1.3,-0.67 1.3,0.68, height 1.1
TI_Stacked_Overlay_Small [mil]
  silkscreen extent -418,-98 418,98
TO-277A [mm] "Vishay"
  rect 1.4x1.27 smd: 1(-1.04,1.83) 2(1.04,1.83)
  rect 4.72x4.8 smd: 3(0,-1.883)
  silkscreen extent -2.7,1.45 -2.4,1.75, body extent -2.35,-4.2 2.4,2.45, height 1.2
TRANS_DFN5 [mm] "OnSemi recommended land pattern Case 488AA Issue G dated 23 APR 2012"
  rect 1x0.75 smd mask+0.051: 1(-2.748,1.905) 2(-2.748,0.635) 3(-2.748,-0.635) 4(-2.748,-1.905) 5(2.748,-1.905) 6(2.748,1.905)
  Top Layer region: -1.282,2.28 2.773,2.28 2.773,-2.28 -1.282,-2.28
  Top Layer region: -0.858,2.775 0.047,2.775 0.047,-2.775 -0.858,-2.775
  silkscreen extent -3.21,-2.68 -1.35,2.93, body extent -3.05,-2.57 3.1,2.58, height 1.13
WEEE_Minimum [mil] "WEEElie bin"
  silkscreen extent -95,-172 99,104
XAL1510 [mm] "COILCRAFT"
  rect 3.18x14.1 smd: 1(-5.3,0) 2(5.3,0)
  silkscreen extent -7.8,-8.3 7.8,8.2, body extent -7.7,-8.2 7.7,8.2, height 11
XAL7070 [mm] "COILCRAFT"
  rect 1.63x7.33 smd: 1(-2.285,0) 2(2.285,0)
  silkscreen extent -3.8,-4 3.8,4, body extent -3.8,-4 3.8,4, height 7

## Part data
C1 C22 C50 C71 C81 C86 C87: library part CMP-0006326-2, "CAP, CERM, 0.1 uF, 50 V, +/- 20%, X7R, AEC-Q200 Grade 1, 0402", Cap_Case=0402, Manufacturer=TDK, Supplier Part Number 1=445-12271-1-ND, TempCo=X7R, Tolerance_%=20%, Value1=Unknown, Value2=50V, ValueDisplayed=0.1uF
C2 C3 C4 C5 C6 C7 C8 C9 C10 C11 C12 C13 C19: library part CMP-0006641-2, "CAP, CERM, 0.1 uF, 16 V, +/- 10%, X7R, 0402", Cap_Case=0402, Manufacturer=MuRata, PartNumber=GRM155R71C104KA88D, Supplier Part Number 1=490-3261-1-ND, TempCo=X7R, Tolerance_%=10%, Value1=Unknown, Value2=16V, ValueDisplayed=0.1uF
C14 C20 C34: library part CMP-0006639-2, "CAP, CERM, 0.01 uF, 16 V, +/- 10%, X7R, 0402", Cap_Case=0402, Manufacturer=MuRata, PartNumber=GRM155R71C103KA01D, Supplier Part Number 1=490-1313-1-ND, TempCo=X7R, Tolerance_%=10%, Value1=Unknown, Value2=16V, ValueDisplayed=0.01uF
C15 C18 C82 C84: library part CMP-0007468-5, "CAP, CERM, 0.01 uF, 100 V, +/- 10%, X7R, 0603", Cap_Case=0603, Manufacturer=MuRata, Supplier Part Number 1=GRM188R72A103KA01D-ND, TempCo=X7R, Tolerance_%=10%, Value1=Unknown, Value2=100V, ValueDisplayed=0.01uF
C16: library part CMP-0006594-2, "CAP, CERM, 2.2 uF, 16 V, +/- 10%, X5R, 0402", Cap_Case=0402, Manufacturer=MuRata, PartNumber=GRM155R61C225KE11D, Supplier Part Number 1=490-10695-1-ND, TempCo=X5R, Tolerance_%=10%, Value1=Unknown, Value2=16V, ValueDisplayed=2.2uF
C17: library part CMP-0006272-2, "CAP, CERM, 1 uF, 16 V, +/- 10%, X5R, 0402", Cap_Case=0402, Manufacturer=TDK, PartNumber=C1005X5R1C105K050BC, Supplier Part Number 1=445-4978-1-ND, TempCo=X5R, Tolerance_%=10%, Value1=Unknown, Value2=16V, ValueDisplayed=1uF
C21 C52 C58 C60 C66 C75 C76 C77: library part CMP-0006314-2, "CAP, CERM, 1000 pF, 50 V, +/- 10%, X7R, AEC-Q200 Grade 1, 0402", Cap_Case=0402, Manufacturer=TDK, Supplier Part Number 1=445-5605-1-ND, TempCo=X7R, Tolerance_%=10%, Value1="2.25564 ohm", Value2=50V, ValueDisplayed=1000pF
C23: library part CMP-0006906-5, "CAP, CERM, 2.2 uF, 10 V, +/- 10%, X5R, 0603", Cap_Case=0603, Manufacturer=Kemet, PartNumber=C0603C225K8PACTU, Supplier Part Number 1=399-4911-1-ND, TempCo=X5R, Tolerance_%=10%, Value1=Unknown, Value2=10V, ValueDisplayed=2.2uF
C24 C26: library part CMP-0006248-2, "CAP, CERM, 22 pF, 50 V, +/- 5%, C0G/NP0, 0402", Cap_Case=0402, Manufacturer=TDK, PartNumber=C1005C0G1H220J050BA, Supplier Part Number 1=445-1239-1-ND, TempCo=C0G/NP0, Tolerance_%=5%, Value1=Unknown, Value2=50V, ValueDisplayed=22pF
C25: library part CMP-0006949-5, "CAP, CERM, 4.7 uF, 10 V, +/- 10%, X5R, 0603", Cap_Case=0603, Manufacturer=Kemet, PartNumber=C0603C475K8PACTU, Supplier Part Number 1=399-5503-1-ND, TempCo=X5R, Tolerance_%=10%, Value1="0.006 ohm", Value2=10V, ValueDisplayed=4.7uF
C27 C38: library part CMP-0007224-4, "CAP, CERM, 56 pF, 50 V, +/- 5%, C0G/NP0, 0603", Cap_Case=0603, Manufacturer=MuRata, PartNumber=GRM1885C1H560JA01D, Supplier Part Number 1=490-1421-1-ND, TempCo=C0G/NP0, Tolerance_%=5%, Value1=Unknown, Value2=50V, ValueDisplayed=56pF
C28: library part CMP-0007146-4, "CAP, CERM, 4700 pF, 50 V, +/- 10%, X7R, AEC-Q200 Grade 1, 0603", Cap_Case=0603, Manufacturer=MuRata, PartNumber=GCM188R71H472KA37D, Supplier Part Number 1=490-4932-1-ND, TempCo=X7R, Tolerance_%=10%, Value1=Unknown, Value2=50V, ValueDisplayed=4700pF
C29: library part CMP-0007144-4, "CAP, CERM, 0.1 uF, 50 V, +/- 10%, X7R, 0603", Cap_Case=0603, Manufacturer=MuRata, PartNumber=GCM188R71H104KA57D, Supplier Part Number 1=490-4779-1-ND, TempCo=X7R, Tolerance_%=10%, Value1="0.02 ohm", Value2=50V, ValueDisplayed=0.1uF
C30 C31: library part CMP-0006752-5, "CAP, CERM, 0.1 uF, 25 V, +/- 5%, X7R, 0603", Cap_Case=0603, Manufacturer=AVX, PartNumber=06033C104JAT2A, Supplier Part Number 1=478-3713-1-ND, TempCo=X7R, Tolerance_%=5%, Value1="0.05 ohm", Value2=25V, ValueDisplayed=0.1uF
C32 C42 C43 C44 C46 C47 C48 C62 C63: library part CMP-0009164-2, "CAP, CERM, 10 uF, 50 V, +/- 10%, X7S, AEC-Q200 Grade 1, 1210", Cap_Case=1210_280, Manufacturer=TDK, Supplier Part Number 1=445-7004-1-ND, TempCo=X7S, Tolerance_%=10%, Value1="0.002827 ohm", Value2=50V, ValueDisplayed=10uF
C35: library part CMP-0006292-2, "CAP, CERM, 0.01 uF, 16 V, +/- 10%, X7R, 0402", Cap_Case=0402, Manufacturer=TDK, PartNumber=C1005X7R1C103K050BA, Supplier Part Number 1=445-1262-1-ND, TempCo=X7R, Tolerance_%=10%, Value1="0.0623 ohm", Value2=16V, ValueDisplayed=0.01uF
C36 C37 C89: library part CMP-0008811-2, "CAP, CERM, 22 uF, 10 V, +/- 10%, X7R, AEC-Q200 Grade 1, 1206", Cap_Case=1206, Manufacturer=MuRata, TempCo=X7R, Tolerance_%=10%, Value1=Unknown, Value2=10V, ValueDisplayed=22uF
C39: library part CMP-0007136-5, "CAP, CERM, 1 uF, 16 V, +/- 10%, X7R, AEC-Q200 Grade 1, 0603", Cap_Case=0603, Manufacturer=MuRata, PartNumber=GCM188R71C105KA64D, Supplier Part Number 1=490-5241-6-ND, TempCo=X7R, Tolerance_%=10%, Value1=Unknown, Value2=16V, ValueDisplayed=1uF
C40: library part CMP-0007136-5, "CAP, CERM, 1 uF, 16 V, +/- 10%, X7R, AEC-Q200 Grade 1, 0603", Cap_Case=0603, Manufacturer=MuRata, Supplier Part Number 1=490-5241-6-ND, TempCo=X7R, Tolerance_%=10%, Value1=Unknown, Value2=16V, ValueDisplayed=1uF
C41: library part CMP-0011177-2, "CAP, AL, 100 uF, 50 V, +/- 20%, 0.34 ohm, AEC-Q200 Grade 2, SMD", Cap_Case=F, Manufacturer=Panasonic, Supplier Part Number 1=PCE3809CT-ND, Tolerance_%=20%, Value1="0.34 ohm", Value2=50V, ValueDisplayed=100uF
C45: library part CMP-0008786-2, "CAP, CERM, 1 uF, 50 V, +/- 10%, X7R, AEC-Q200 Grade 1, 1206", Cap_Case=1206_180, Manufacturer=TDK, Supplier Part Number 1=445-5702-1-ND, TempCo=X7R, Tolerance_%=10%, Value1="0.009289 ohm", Value2=50V, ValueDisplayed=1uF
C49 C53 C54 C64 C67 C68 C69 C88: library part CMP-0009150-2, "CAP, CERM, 4.7 uF, 100 V, +/- 10%, X7S, AEC-Q200 Grade 1, 1210", Cap_Case=1210_220, Manufacturer=TDK, Supplier Part Number 1=445-7005-1-ND, TempCo=X7S, Tolerance_%=10%, Value1="0.004236 ohm", Value2=100V, ValueDisplayed=4.7uF
C51 C59 C72 C80: library part CMP-0007099-4, "CAP, CERM, 0.1 uF, 100 V, +/- 10%, X7S, AEC-Q200 Grade 1, 0603", Cap_Case=0603, Manufacturer=TDK, Supplier Part Number 1=445-6938-1-ND, TempCo=X7S, Tolerance_%=10%, Value1="0.04959 ohm", Value2=100V, ValueDisplayed=0.1uF
C55: library part CMP-0008790-2, "CAP, CERM, 2.2 uF, 100 V, +/- 10%, X7S, AEC-Q200 Grade 1, 1206", Cap_Case=1206_180, Manufacturer=TDK, Supplier Part Number 1=445-6994-1-ND, TempCo=X7S, Tolerance_%=10%, Value1="0.005718 ohm", Value2=100V, ValueDisplayed=2.2uF
C56 C70: library part CMP-0008778-2, "CAP, CERM, 0.1 uF, 100 V, +/- 10%, X7R, AEC-Q200 Grade 1, 1206", Cap_Case=1206_180, Manufacturer=TDK, Supplier Part Number 1=445-5840-1-ND, TempCo=X7R, Tolerance_%=10%, Value1="0.030343 ohm", Value2=100V, ValueDisplayed=0.1uF
C57 C73: library part CMP-0007082-4, "CAP, CERM, 0.01 uF, 100 V, +/- 10%, X7R, AEC-Q200 Grade 1, 0603", Cap_Case=0603, Manufacturer=TDK, PartNumber=CGA3E2X7R2A103K080AA, Supplier Part Number 1=445-5812-1-ND, TempCo=X7R, Tolerance_%=10%, Value1="0.235428 ohm", Value2=100V, ValueDisplayed=0.01uF
C61: library part CMP-0011202-2, "CAP, AL, 22 uF, 100 V, +/- 20%, 1.3 ohm, AEC-Q200 Grade 2, SMD", Cap_Case=F, Manufacturer=Panasonic, Supplier Part Number 1=PCE3845CT-ND, Tolerance_%=20%, Value1="1.3 ohm", Value2=100V, ValueDisplayed=22uF
C65 C74: library part CMP-0007499-4, "CAP, CERM, 2.2 uF, 16 V, +/- 10%, X7R, 0603", Cap_Case=0603, Manufacturer=MuRata, PartNumber=GRM188Z71C225KE43, Supplier Part Number 1=81-GRM188Z71C225KE3D, TempCo=X7R, Tolerance_%=10%, Value1=Unknown, Value2=16V, ValueDisplayed=2.2uF
C78: library part CMP-0007086-4, "CAP, CERM, 0.022 uF, 100 V, +/- 10%, X7R, AEC-Q200 Grade 1, 0603", Cap_Case=0603, Manufacturer=TDK, Supplier Part Number 1=445-5814-1-ND, TempCo=X7R, Tolerance_%=10%, Value1="0.083542 ohm", Value2=100V, ValueDisplayed=0.022uF
C79 C85: library part CMP-0008779-2, "CAP, CERM, 1 uF, 100 V, +/- 10%, X7R, AEC-Q200 Grade 1, 1206", Cap_Case=1206_180, Manufacturer=TDK, Supplier Part Number 1=445-5845-1-ND, TempCo=X7R, Tolerance_%=10%, Value1="0.004575 ohm", Value2=100V, ValueDisplayed=1uF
